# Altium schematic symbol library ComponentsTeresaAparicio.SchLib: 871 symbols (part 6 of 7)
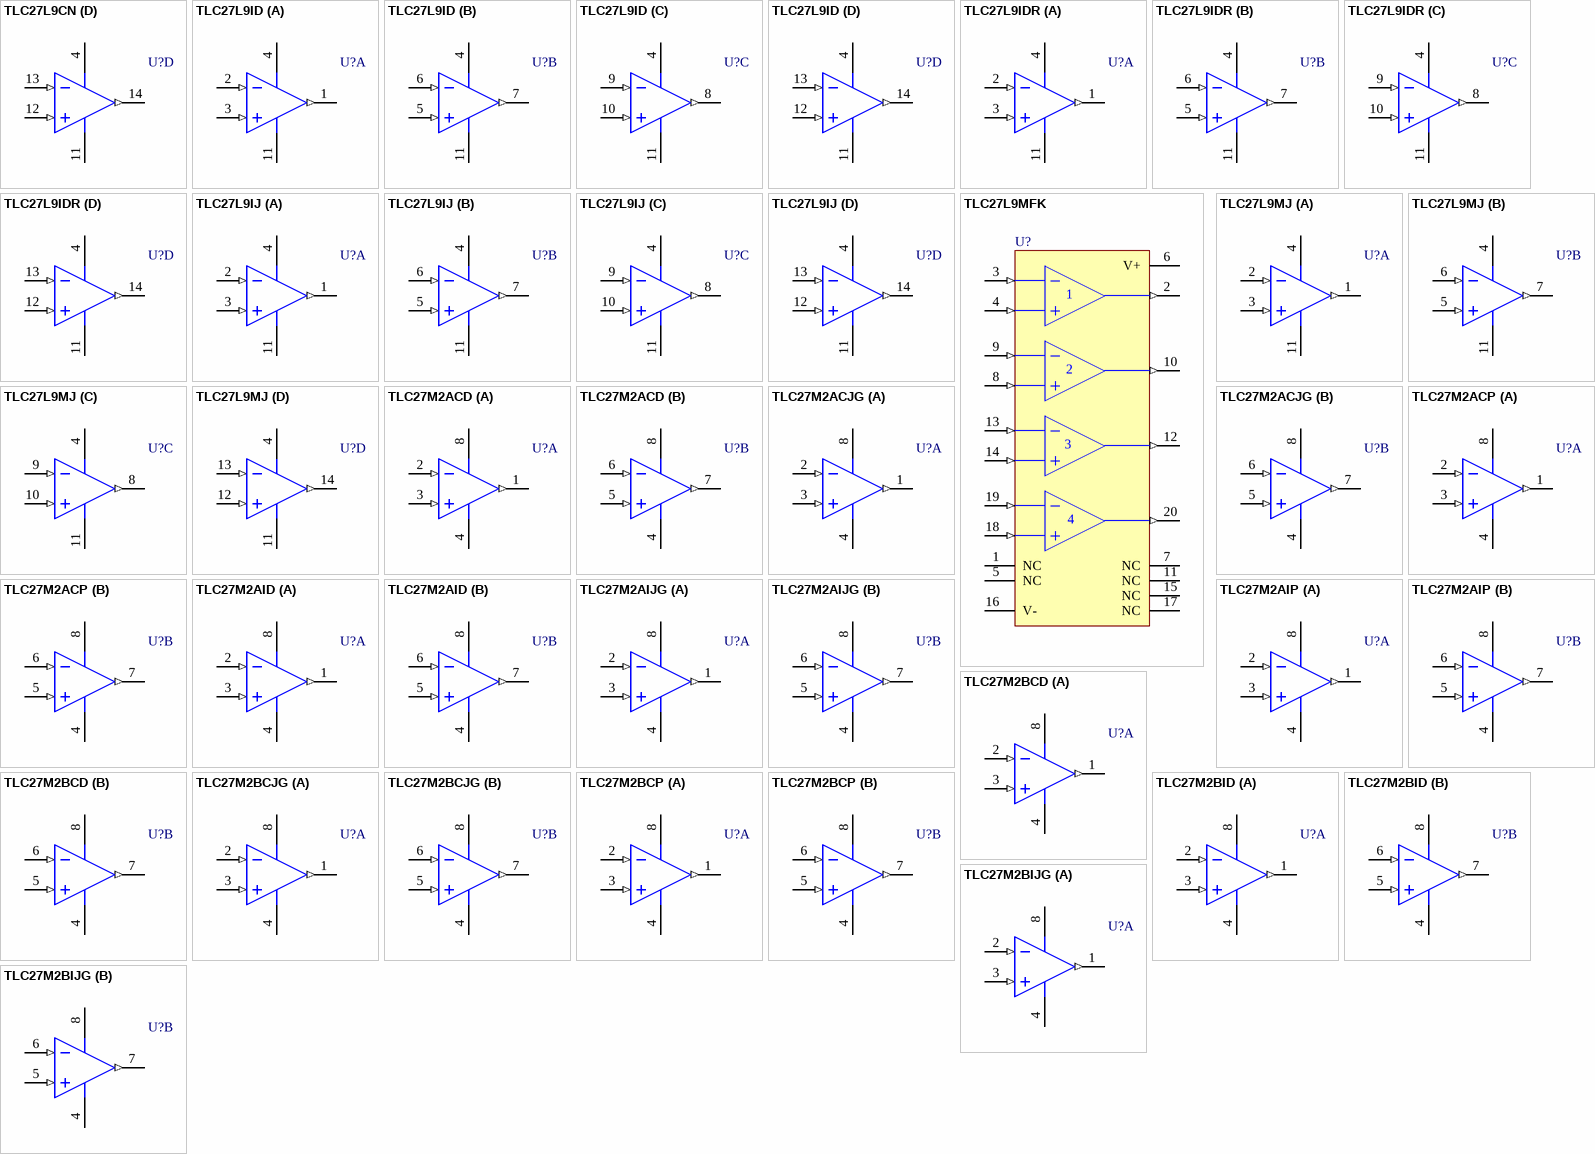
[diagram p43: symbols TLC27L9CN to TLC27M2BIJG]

## TLC27L9MJ
designator U?
LinCMOS Precision Quad Operational Amplifier; ComponentAvailability: Obsolete
footprint J014 (DIP; 14 Leads; Row Spacing 7.62 mm; Pitch 2.54 mm)
3D model J014 (DIP; 14 Leads; Row Spacing 7.62 mm; Pitch 2.54 mm)
pins on every part: 4 V+ (power), 11 V- (power)
part A pins: 1 OUT (out), 2 IN- (in), 3 IN+ (in)
part B pins: 5 IN+ (in), 6 IN- (in), 7 OUT (out)
part C pins: 8 OUT (out), 9 IN- (in), 10 IN+ (in)
part D pins: 12 IN+ (in), 13 IN- (in), 14 OUT (out)

## TLC27M2ACD
designator U?
LinCMOS Precision Dual Operational Amplifier
footprint D008_L (SOIC, 8-Leads, Body 4.9x3.9mm, Pitch 1.27mm, IPC High Density)
footprint D008_M (SOIC, 8-Leads, Body 4.9x3.9mm, Pitch 1.27mm, IPC Low Density)
footprint D008_M (SOIC, 8-Leads, Body 4.9x3.9mm, Pitch 1.27mm, IPC Low Density)
3D model D008 (8-Pin Small Outline Integrated Circuit 1.27 mm Pitch)
pins on every part: 4 GND (power), 8 VDD (power)
part A pins: 1 OUT (out), 2 IN- (in), 3 IN+ (in)
part B pins: 5 IN+ (in), 6 IN- (in), 7 OUT (out)

## TLC27M2ACJG
designator U?
LinCMOS Precision Dual Operational Amplifier
footprint JG008 (DIP; 8 Leads; Row Spacing 7.62 mm; Pitch 2.54 mm)
3D model JG008 (DIP; 8 Leads; Row Spacing 7.62 mm; Pitch 2.54 mm)
pins on every part: 4 GND (power), 8 VDD (power)
part A pins: 1 OUT (out), 2 IN- (in), 3 IN+ (in)
part B pins: 5 IN+ (in), 6 IN- (in), 7 OUT (out)

## TLC27M2ACP
designator U?
LinCMOS Precision Dual Operational Amplifier
footprint P008 (DIP; 8 Leads; Row Spacing 7.62 mm; Pitch 2.54 mm)
3D model P008 (DIP; 8 Leads; Row Spacing 7.62 mm; Pitch 2.54 mm)
pins on every part: 4 GND (power), 8 VDD (power)
part A pins: 1 OUT (out), 2 IN- (in), 3 IN+ (in)
part B pins: 5 IN+ (in), 6 IN- (in), 7 OUT (out)

## TLC27M2AID
designator U?
LinCMOS Precision Dual Operational Amplifier
footprint D008_L (SOIC, 8-Leads, Body 4.9x3.9mm, Pitch 1.27mm, IPC High Density)
footprint D008_M (SOIC, 8-Leads, Body 4.9x3.9mm, Pitch 1.27mm, IPC Low Density)
footprint D008_M (SOIC, 8-Leads, Body 4.9x3.9mm, Pitch 1.27mm, IPC Low Density)
3D model D008 (8-Pin Small Outline Integrated Circuit 1.27 mm Pitch)
pins on every part: 4 GND (power), 8 VDD (power)
part A pins: 1 OUT (out), 2 IN- (in), 3 IN+ (in)
part B pins: 5 IN+ (in), 6 IN- (in), 7 OUT (out)

## TLC27M2AIJG
designator U?
LinCMOS Precision Dual Operational Amplifier
footprint JG008 (DIP; 8 Leads; Row Spacing 7.62 mm; Pitch 2.54 mm)
3D model JG008 (DIP; 8 Leads; Row Spacing 7.62 mm; Pitch 2.54 mm)
pins on every part: 4 GND (power), 8 VDD (power)
part A pins: 1 OUT (out), 2 IN- (in), 3 IN+ (in)
part B pins: 5 IN+ (in), 6 IN- (in), 7 OUT (out)

## TLC27M2AIP
designator U?
LinCMOS Precision Dual Operational Amplifier
footprint P008 (DIP; 8 Leads; Row Spacing 7.62 mm; Pitch 2.54 mm)
3D model P008 (DIP; 8 Leads; Row Spacing 7.62 mm; Pitch 2.54 mm)
pins on every part: 4 GND (power), 8 VDD (power)
part A pins: 1 OUT (out), 2 IN- (in), 3 IN+ (in)
part B pins: 5 IN+ (in), 6 IN- (in), 7 OUT (out)

## TLC27M2BCD
designator U?
LinCMOS Precision Dual Operational Amplifier
footprint D008_L (SOIC, 8-Leads, Body 4.9x3.9mm, Pitch 1.27mm, IPC High Density)
footprint D008_M (SOIC, 8-Leads, Body 4.9x3.9mm, Pitch 1.27mm, IPC Low Density)
footprint D008_M (SOIC, 8-Leads, Body 4.9x3.9mm, Pitch 1.27mm, IPC Low Density)
3D model D008 (8-Pin Small Outline Integrated Circuit 1.27 mm Pitch)
pins on every part: 4 GND (power), 8 VDD (power)
part A pins: 1 OUT (out), 2 IN- (in), 3 IN+ (in)
part B pins: 5 IN+ (in), 6 IN- (in), 7 OUT (out)

## TLC27M2BCJG
designator U?
LinCMOS Precision Dual Operational Amplifier
footprint JG008 (DIP; 8 Leads; Row Spacing 7.62 mm; Pitch 2.54 mm)
3D model JG008 (DIP; 8 Leads; Row Spacing 7.62 mm; Pitch 2.54 mm)
pins on every part: 4 GND (power), 8 VDD (power)
part A pins: 1 OUT (out), 2 IN- (in), 3 IN+ (in)
part B pins: 5 IN+ (in), 6 IN- (in), 7 OUT (out)

## TLC27M2BCP
designator U?
LinCMOS Precision Dual Operational Amplifier
footprint P008 (DIP; 8 Leads; Row Spacing 7.62 mm; Pitch 2.54 mm)
3D model P008 (DIP; 8 Leads; Row Spacing 7.62 mm; Pitch 2.54 mm)
pins on every part: 4 GND (power), 8 VDD (power)
part A pins: 1 OUT (out), 2 IN- (in), 3 IN+ (in)
part B pins: 5 IN+ (in), 6 IN- (in), 7 OUT (out)

## TLC27M2BID
designator U?
LinCMOS Precision Dual Operational Amplifier
footprint D008_L (SOIC, 8-Leads, Body 4.9x3.9mm, Pitch 1.27mm, IPC High Density)
footprint D008_M (SOIC, 8-Leads, Body 4.9x3.9mm, Pitch 1.27mm, IPC Low Density)
footprint D008_M (SOIC, 8-Leads, Body 4.9x3.9mm, Pitch 1.27mm, IPC Low Density)
3D model D008 (8-Pin Small Outline Integrated Circuit 1.27 mm Pitch)
pins on every part: 4 GND (power), 8 VDD (power)
part A pins: 1 OUT (out), 2 IN- (in), 3 IN+ (in)
part B pins: 5 IN+ (in), 6 IN- (in), 7 OUT (out)

## TLC27M2BIJG
designator U?
LinCMOS Precision Dual Operational Amplifier
footprint JG008 (DIP; 8 Leads; Row Spacing 7.62 mm; Pitch 2.54 mm)
3D model JG008 (DIP; 8 Leads; Row Spacing 7.62 mm; Pitch 2.54 mm)
pins on every part: 4 GND (power), 8 VDD (power)
part A pins: 1 OUT (out), 2 IN- (in), 3 IN+ (in)
part B pins: 5 IN+ (in), 6 IN- (in), 7 OUT (out)

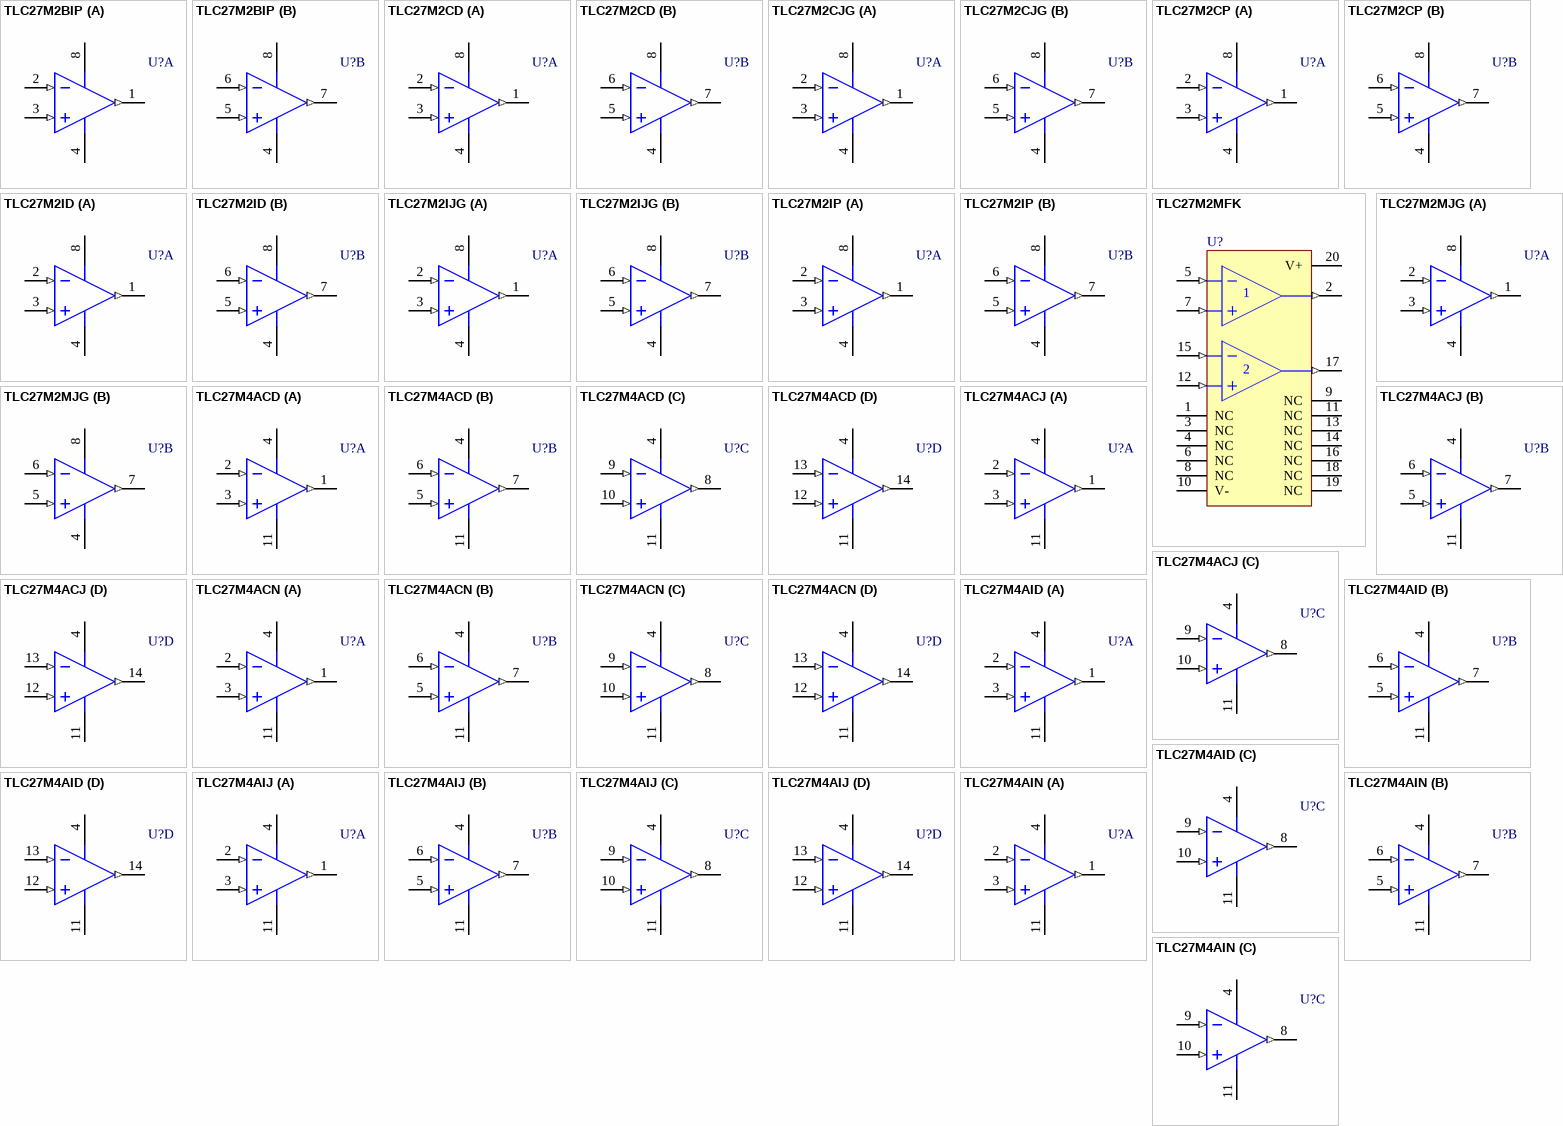
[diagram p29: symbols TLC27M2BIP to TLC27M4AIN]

## TLC27M2BIP
designator U?
LinCMOS Precision Dual Operational Amplifier
footprint P008 (DIP; 8 Leads; Row Spacing 7.62 mm; Pitch 2.54 mm)
3D model P008 (DIP; 8 Leads; Row Spacing 7.62 mm; Pitch 2.54 mm)
pins on every part: 4 GND (power), 8 VDD (power)
part A pins: 1 OUT (out), 2 IN- (in), 3 IN+ (in)
part B pins: 5 IN+ (in), 6 IN- (in), 7 OUT (out)

## TLC27M2CD
designator U?
LinCMOS Precision Dual Operational Amplifier
footprint D008_L (SOIC, 8-Leads, Body 4.9x3.9mm, Pitch 1.27mm, IPC High Density)
footprint D008_M (SOIC, 8-Leads, Body 4.9x3.9mm, Pitch 1.27mm, IPC Low Density)
footprint D008_M (SOIC, 8-Leads, Body 4.9x3.9mm, Pitch 1.27mm, IPC Low Density)
3D model D008 (8-Pin Small Outline Integrated Circuit 1.27 mm Pitch)
pins on every part: 4 GND (power), 8 VDD (power)
part A pins: 1 OUT (out), 2 IN- (in), 3 IN+ (in)
part B pins: 5 IN+ (in), 6 IN- (in), 7 OUT (out)

## TLC27M2CJG
designator U?
LinCMOS Precision Dual Operational Amplifier
footprint JG008 (DIP; 8 Leads; Row Spacing 7.62 mm; Pitch 2.54 mm)
3D model JG008 (DIP; 8 Leads; Row Spacing 7.62 mm; Pitch 2.54 mm)
pins on every part: 4 GND (power), 8 VDD (power)
part A pins: 1 OUT (out), 2 IN- (in), 3 IN+ (in)
part B pins: 5 IN+ (in), 6 IN- (in), 7 OUT (out)

## TLC27M2CP
designator U?
LinCMOS Precision Dual Operational Amplifier
footprint P008 (DIP; 8 Leads; Row Spacing 7.62 mm; Pitch 2.54 mm)
3D model P008 (DIP; 8 Leads; Row Spacing 7.62 mm; Pitch 2.54 mm)
pins on every part: 4 GND (power), 8 VDD (power)
part A pins: 1 OUT (out), 2 IN- (in), 3 IN+ (in)
part B pins: 5 IN+ (in), 6 IN- (in), 7 OUT (out)

## TLC27M2ID
designator U?
LinCMOS Precision Dual Operational Amplifier
footprint D008_L (SOIC, 8-Leads, Body 4.9x3.9mm, Pitch 1.27mm, IPC High Density)
footprint D008_M (SOIC, 8-Leads, Body 4.9x3.9mm, Pitch 1.27mm, IPC Low Density)
footprint D008_M (SOIC, 8-Leads, Body 4.9x3.9mm, Pitch 1.27mm, IPC Low Density)
3D model D008 (8-Pin Small Outline Integrated Circuit 1.27 mm Pitch)
pins on every part: 4 GND (power), 8 VDD (power)
part A pins: 1 OUT (out), 2 IN- (in), 3 IN+ (in)
part B pins: 5 IN+ (in), 6 IN- (in), 7 OUT (out)

## TLC27M2IJG
designator U?
LinCMOS Precision Dual Operational Amplifier
footprint JG008 (DIP; 8 Leads; Row Spacing 7.62 mm; Pitch 2.54 mm)
3D model JG008 (DIP; 8 Leads; Row Spacing 7.62 mm; Pitch 2.54 mm)
pins on every part: 4 GND (power), 8 VDD (power)
part A pins: 1 OUT (out), 2 IN- (in), 3 IN+ (in)
part B pins: 5 IN+ (in), 6 IN- (in), 7 OUT (out)

## TLC27M2IP
designator U?
LinCMOS Precision Dual Operational Amplifier
footprint P008 (DIP; 8 Leads; Row Spacing 7.62 mm; Pitch 2.54 mm)
3D model P008 (DIP; 8 Leads; Row Spacing 7.62 mm; Pitch 2.54 mm)
pins on every part: 4 GND (power), 8 VDD (power)
part A pins: 1 OUT (out), 2 IN- (in), 3 IN+ (in)
part B pins: 5 IN+ (in), 6 IN- (in), 7 OUT (out)

## TLC27M2MFK
designator U?
LinCMOS Precision Dual Operational Amplifier; ComponentAvailability: Obsolete
footprint FK020 (Leadless Chip Carrier; 20 Terminals; Body 8.9 x 8.9 mm)
pins: 1 NC, 2 OUT (out), 3 NC, 4 NC, 5 IN- (in), 6 NC, 7 IN+ (in), 8 NC, 9 NC, 10 V- (power), 11 NC, 12 IN+ (in), 13 NC, 14 NC, 15 IN- (in), 16 NC, 17 OUT (out), 18 NC, 19 NC, 20 V+ (power)

## TLC27M2MJG
designator U?
LinCMOS Precision Dual Operational Amplifier; ComponentAvailability: Obsolete
footprint JG008 (DIP; 8 Leads; Row Spacing 7.62 mm; Pitch 2.54 mm)
3D model JG008 (DIP; 8 Leads; Row Spacing 7.62 mm; Pitch 2.54 mm)
pins on every part: 4 GND (power), 8 VDD (power)
part A pins: 1 OUT (out), 2 IN- (in), 3 IN+ (in)
part B pins: 5 IN+ (in), 6 IN- (in), 7 OUT (out)

## TLC27M4ACD
designator U?
LinCMOS Precision Quad Operational Amplifier
footprint D014_N (SOIC, 14-Leads, Body 8.7x3.9mm, Pitch 1.27mm, IPC Medium Density)
footprint D014_L (SOIC, 14-Leads, Body 8.7x3.9mm, Pitch 1.27mm, IPC High Density)
footprint D014_M (SOIC, 14-Leads, Body 8.7x3.9mm, Pitch 1.27mm, IPC Low Density)
3D model D014 (14-Pin Small Outline Integrated Circuit 1.27 mm Pitch)
pins on every part: 4 V+ (power), 11 V- (power)
part A pins: 1 OUT (out), 2 IN- (in), 3 IN+ (in)
part B pins: 5 IN+ (in), 6 IN- (in), 7 OUT (out)
part C pins: 8 OUT (out), 9 IN- (in), 10 IN+ (in)
part D pins: 12 IN+ (in), 13 IN- (in), 14 OUT (out)

## TLC27M4ACJ
designator U?
LinCMOS Precision Quad Operational Amplifier
footprint J014 (DIP; 14 Leads; Row Spacing 7.62 mm; Pitch 2.54 mm)
3D model J014 (DIP; 14 Leads; Row Spacing 7.62 mm; Pitch 2.54 mm)
pins on every part: 4 V+ (power), 11 V- (power)
part A pins: 1 OUT (out), 2 IN- (in), 3 IN+ (in)
part B pins: 5 IN+ (in), 6 IN- (in), 7 OUT (out)
part C pins: 8 OUT (out), 9 IN- (in), 10 IN+ (in)
part D pins: 12 IN+ (in), 13 IN- (in), 14 OUT (out)

## TLC27M4ACN
designator U?
LinCMOS Precision Quad Operational Amplifier
footprint N014 (DIP; 14 Leads; Row Spacing 7.62 mm; Pitch 2.54 mm)
3D model N014 (DIP; 14 Leads; Row Spacing 7.62 mm; Pitch 2.54 mm)
pins on every part: 4 V+ (power), 11 V- (power)
part A pins: 1 OUT (out), 2 IN- (in), 3 IN+ (in)
part B pins: 5 IN+ (in), 6 IN- (in), 7 OUT (out)
part C pins: 8 OUT (out), 9 IN- (in), 10 IN+ (in)
part D pins: 12 IN+ (in), 13 IN- (in), 14 OUT (out)

## TLC27M4AID
designator U?
LinCMOS Precision Quad Operational Amplifier
footprint D014_N (SOIC, 14-Leads, Body 8.7x3.9mm, Pitch 1.27mm, IPC Medium Density)
footprint D014_L (SOIC, 14-Leads, Body 8.7x3.9mm, Pitch 1.27mm, IPC High Density)
footprint D014_M (SOIC, 14-Leads, Body 8.7x3.9mm, Pitch 1.27mm, IPC Low Density)
3D model D014 (14-Pin Small Outline Integrated Circuit 1.27 mm Pitch)
pins on every part: 4 V+ (power), 11 V- (power)
part A pins: 1 OUT (out), 2 IN- (in), 3 IN+ (in)
part B pins: 5 IN+ (in), 6 IN- (in), 7 OUT (out)
part C pins: 8 OUT (out), 9 IN- (in), 10 IN+ (in)
part D pins: 12 IN+ (in), 13 IN- (in), 14 OUT (out)

## TLC27M4AIJ
designator U?
LinCMOS Precision Quad Operational Amplifier
footprint J014 (DIP; 14 Leads; Row Spacing 7.62 mm; Pitch 2.54 mm)
3D model J014 (DIP; 14 Leads; Row Spacing 7.62 mm; Pitch 2.54 mm)
pins on every part: 4 V+ (power), 11 V- (power)
part A pins: 1 OUT (out), 2 IN- (in), 3 IN+ (in)
part B pins: 5 IN+ (in), 6 IN- (in), 7 OUT (out)
part C pins: 8 OUT (out), 9 IN- (in), 10 IN+ (in)
part D pins: 12 IN+ (in), 13 IN- (in), 14 OUT (out)

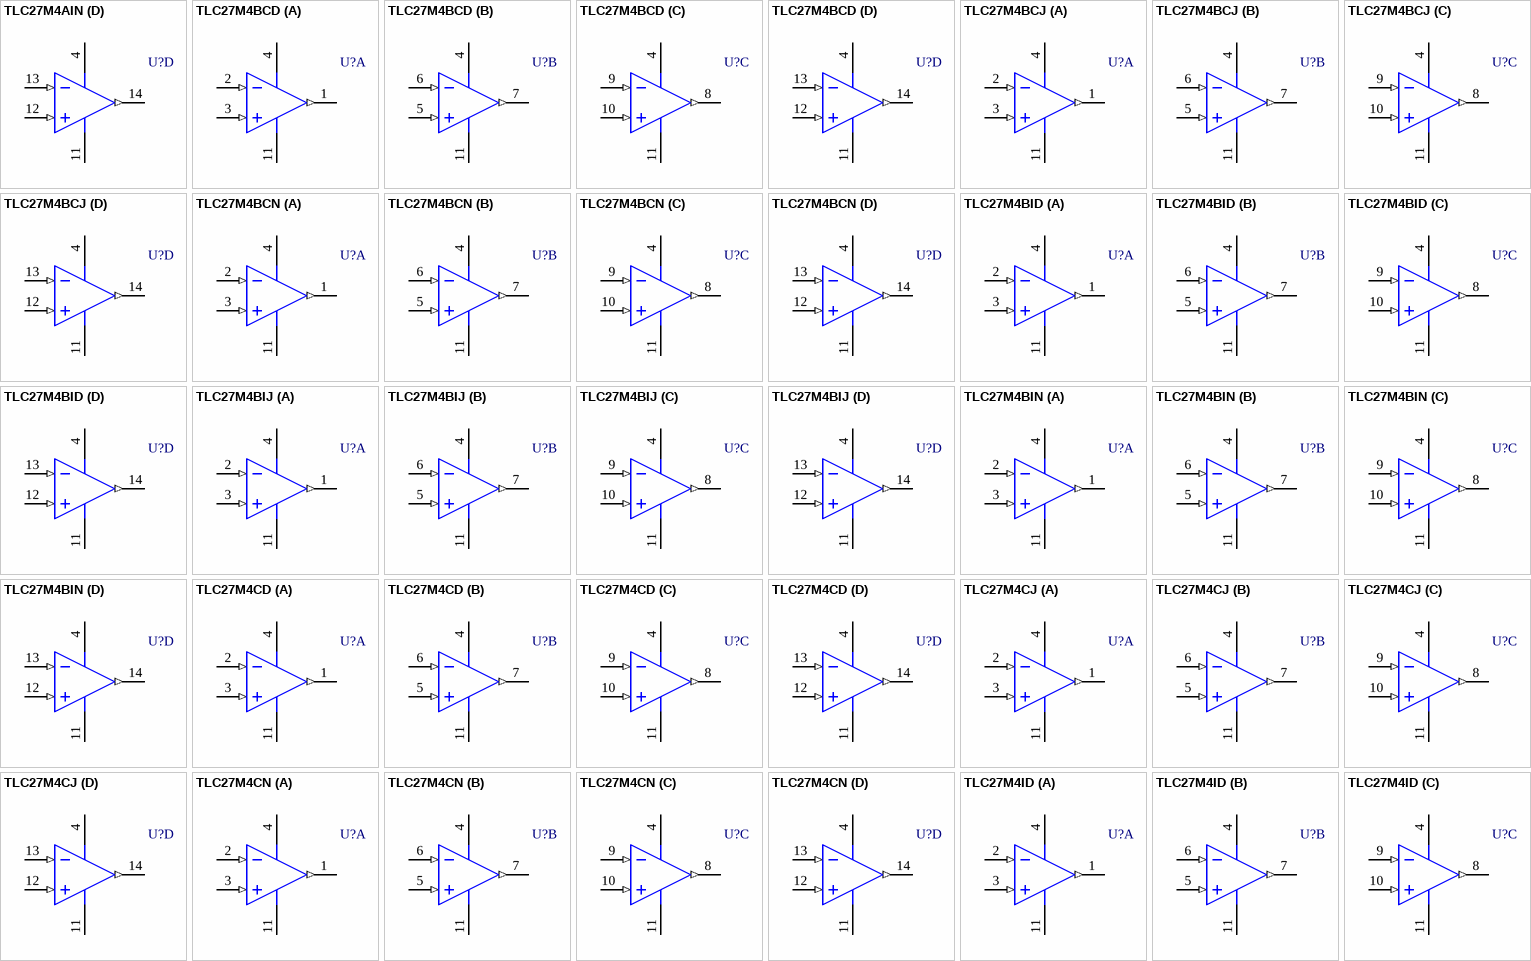
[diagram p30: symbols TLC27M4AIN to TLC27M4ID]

## TLC27M4AIN
designator U?
LinCMOS Precision Quad Operational Amplifier
footprint N014 (DIP; 14 Leads; Row Spacing 7.62 mm; Pitch 2.54 mm)
3D model N014 (DIP; 14 Leads; Row Spacing 7.62 mm; Pitch 2.54 mm)
pins on every part: 4 V+ (power), 11 V- (power)
part A pins: 1 OUT (out), 2 IN- (in), 3 IN+ (in)
part B pins: 5 IN+ (in), 6 IN- (in), 7 OUT (out)
part C pins: 8 OUT (out), 9 IN- (in), 10 IN+ (in)
part D pins: 12 IN+ (in), 13 IN- (in), 14 OUT (out)

## TLC27M4BCD
designator U?
LinCMOS Precision Quad Operational Amplifier
footprint D014_N (SOIC, 14-Leads, Body 8.7x3.9mm, Pitch 1.27mm, IPC Medium Density)
footprint D014_L (SOIC, 14-Leads, Body 8.7x3.9mm, Pitch 1.27mm, IPC High Density)
footprint D014_M (SOIC, 14-Leads, Body 8.7x3.9mm, Pitch 1.27mm, IPC Low Density)
3D model D014 (14-Pin Small Outline Integrated Circuit 1.27 mm Pitch)
pins on every part: 4 V+ (power), 11 V- (power)
part A pins: 1 OUT (out), 2 IN- (in), 3 IN+ (in)
part B pins: 5 IN+ (in), 6 IN- (in), 7 OUT (out)
part C pins: 8 OUT (out), 9 IN- (in), 10 IN+ (in)
part D pins: 12 IN+ (in), 13 IN- (in), 14 OUT (out)

## TLC27M4BCJ
designator U?
LinCMOS Precision Quad Operational Amplifier
footprint J014 (DIP; 14 Leads; Row Spacing 7.62 mm; Pitch 2.54 mm)
3D model J014 (DIP; 14 Leads; Row Spacing 7.62 mm; Pitch 2.54 mm)
pins on every part: 4 V+ (power), 11 V- (power)
part A pins: 1 OUT (out), 2 IN- (in), 3 IN+ (in)
part B pins: 5 IN+ (in), 6 IN- (in), 7 OUT (out)
part C pins: 8 OUT (out), 9 IN- (in), 10 IN+ (in)
part D pins: 12 IN+ (in), 13 IN- (in), 14 OUT (out)

## TLC27M4BCN
designator U?
LinCMOS Precision Quad Operational Amplifier
footprint N014 (DIP; 14 Leads; Row Spacing 7.62 mm; Pitch 2.54 mm)
3D model N014 (DIP; 14 Leads; Row Spacing 7.62 mm; Pitch 2.54 mm)
pins on every part: 4 V+ (power), 11 V- (power)
part A pins: 1 OUT (out), 2 IN- (in), 3 IN+ (in)
part B pins: 5 IN+ (in), 6 IN- (in), 7 OUT (out)
part C pins: 8 OUT (out), 9 IN- (in), 10 IN+ (in)
part D pins: 12 IN+ (in), 13 IN- (in), 14 OUT (out)

## TLC27M4BID
designator U?
LinCMOS Precision Quad Operational Amplifier
footprint D014_N (SOIC, 14-Leads, Body 8.7x3.9mm, Pitch 1.27mm, IPC Medium Density)
footprint D014_L (SOIC, 14-Leads, Body 8.7x3.9mm, Pitch 1.27mm, IPC High Density)
footprint D014_M (SOIC, 14-Leads, Body 8.7x3.9mm, Pitch 1.27mm, IPC Low Density)
3D model D014 (14-Pin Small Outline Integrated Circuit 1.27 mm Pitch)
pins on every part: 4 V+ (power), 11 V- (power)
part A pins: 1 OUT (out), 2 IN- (in), 3 IN+ (in)
part B pins: 5 IN+ (in), 6 IN- (in), 7 OUT (out)
part C pins: 8 OUT (out), 9 IN- (in), 10 IN+ (in)
part D pins: 12 IN+ (in), 13 IN- (in), 14 OUT (out)

## TLC27M4BIJ
designator U?
LinCMOS Precision Quad Operational Amplifier
footprint J014 (DIP; 14 Leads; Row Spacing 7.62 mm; Pitch 2.54 mm)
3D model J014 (DIP; 14 Leads; Row Spacing 7.62 mm; Pitch 2.54 mm)
pins on every part: 4 V+ (power), 11 V- (power)
part A pins: 1 OUT (out), 2 IN- (in), 3 IN+ (in)
part B pins: 5 IN+ (in), 6 IN- (in), 7 OUT (out)
part C pins: 8 OUT (out), 9 IN- (in), 10 IN+ (in)
part D pins: 12 IN+ (in), 13 IN- (in), 14 OUT (out)

## TLC27M4BIN
designator U?
LinCMOS Precision Quad Operational Amplifier
footprint N014 (DIP; 14 Leads; Row Spacing 7.62 mm; Pitch 2.54 mm)
3D model N014 (DIP; 14 Leads; Row Spacing 7.62 mm; Pitch 2.54 mm)
pins on every part: 4 V+ (power), 11 V- (power)
part A pins: 1 OUT (out), 2 IN- (in), 3 IN+ (in)
part B pins: 5 IN+ (in), 6 IN- (in), 7 OUT (out)
part C pins: 8 OUT (out), 9 IN- (in), 10 IN+ (in)
part D pins: 12 IN+ (in), 13 IN- (in), 14 OUT (out)

## TLC27M4CD
designator U?
LinCMOS Precision Quad Operational Amplifier
footprint D014_N (SOIC, 14-Leads, Body 8.7x3.9mm, Pitch 1.27mm, IPC Medium Density)
footprint D014_L (SOIC, 14-Leads, Body 8.7x3.9mm, Pitch 1.27mm, IPC High Density)
footprint D014_M (SOIC, 14-Leads, Body 8.7x3.9mm, Pitch 1.27mm, IPC Low Density)
3D model D014 (14-Pin Small Outline Integrated Circuit 1.27 mm Pitch)
pins on every part: 4 V+ (power), 11 V- (power)
part A pins: 1 OUT (out), 2 IN- (in), 3 IN+ (in)
part B pins: 5 IN+ (in), 6 IN- (in), 7 OUT (out)
part C pins: 8 OUT (out), 9 IN- (in), 10 IN+ (in)
part D pins: 12 IN+ (in), 13 IN- (in), 14 OUT (out)

## TLC27M4CJ
designator U?
LinCMOS Precision Quad Operational Amplifier
footprint J014 (DIP; 14 Leads; Row Spacing 7.62 mm; Pitch 2.54 mm)
3D model J014 (DIP; 14 Leads; Row Spacing 7.62 mm; Pitch 2.54 mm)
pins on every part: 4 V+ (power), 11 V- (power)
part A pins: 1 OUT (out), 2 IN- (in), 3 IN+ (in)
part B pins: 5 IN+ (in), 6 IN- (in), 7 OUT (out)
part C pins: 8 OUT (out), 9 IN- (in), 10 IN+ (in)
part D pins: 12 IN+ (in), 13 IN- (in), 14 OUT (out)

## TLC27M4CN
designator U?
LinCMOS Precision Quad Operational Amplifier
footprint N014 (DIP; 14 Leads; Row Spacing 7.62 mm; Pitch 2.54 mm)
3D model N014 (DIP; 14 Leads; Row Spacing 7.62 mm; Pitch 2.54 mm)
pins on every part: 4 V+ (power), 11 V- (power)
part A pins: 1 OUT (out), 2 IN- (in), 3 IN+ (in)
part B pins: 5 IN+ (in), 6 IN- (in), 7 OUT (out)
part C pins: 8 OUT (out), 9 IN- (in), 10 IN+ (in)
part D pins: 12 IN+ (in), 13 IN- (in), 14 OUT (out)

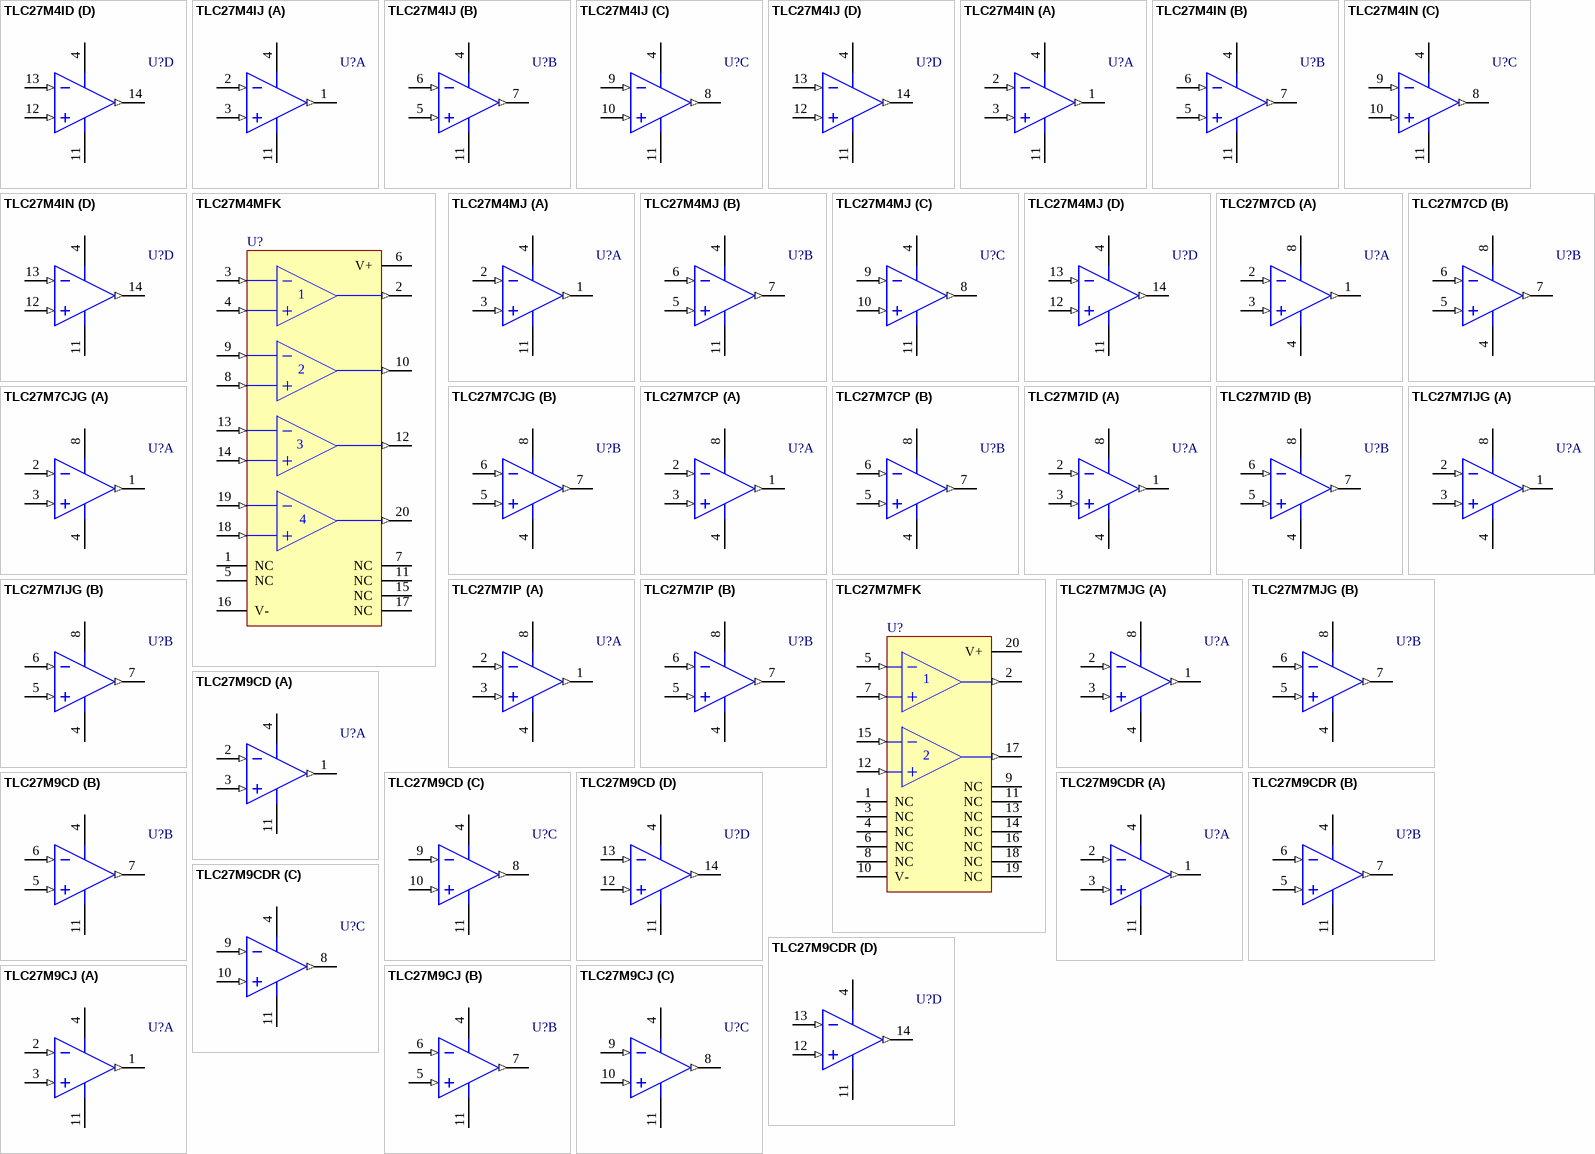
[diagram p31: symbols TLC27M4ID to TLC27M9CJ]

## TLC27M4ID
designator U?
LinCMOS Precision Quad Operational Amplifier
footprint D014_N (SOIC, 14-Leads, Body 8.7x3.9mm, Pitch 1.27mm, IPC Medium Density)
footprint D014_L (SOIC, 14-Leads, Body 8.7x3.9mm, Pitch 1.27mm, IPC High Density)
footprint D014_M (SOIC, 14-Leads, Body 8.7x3.9mm, Pitch 1.27mm, IPC Low Density)
3D model D014 (14-Pin Small Outline Integrated Circuit 1.27 mm Pitch)
pins on every part: 4 V+ (power), 11 V- (power)
part A pins: 1 OUT (out), 2 IN- (in), 3 IN+ (in)
part B pins: 5 IN+ (in), 6 IN- (in), 7 OUT (out)
part C pins: 8 OUT (out), 9 IN- (in), 10 IN+ (in)
part D pins: 12 IN+ (in), 13 IN- (in), 14 OUT (out)

## TLC27M4IJ
designator U?
LinCMOS Precision Quad Operational Amplifier
footprint J014 (DIP; 14 Leads; Row Spacing 7.62 mm; Pitch 2.54 mm)
3D model J014 (DIP; 14 Leads; Row Spacing 7.62 mm; Pitch 2.54 mm)
pins on every part: 4 V+ (power), 11 V- (power)
part A pins: 1 OUT (out), 2 IN- (in), 3 IN+ (in)
part B pins: 5 IN+ (in), 6 IN- (in), 7 OUT (out)
part C pins: 8 OUT (out), 9 IN- (in), 10 IN+ (in)
part D pins: 12 IN+ (in), 13 IN- (in), 14 OUT (out)

## TLC27M4IN
designator U?
LinCMOS Precision Quad Operational Amplifier
footprint N014 (DIP; 14 Leads; Row Spacing 7.62 mm; Pitch 2.54 mm)
3D model N014 (DIP; 14 Leads; Row Spacing 7.62 mm; Pitch 2.54 mm)
pins on every part: 4 V+ (power), 11 V- (power)
part A pins: 1 OUT (out), 2 IN- (in), 3 IN+ (in)
part B pins: 5 IN+ (in), 6 IN- (in), 7 OUT (out)
part C pins: 8 OUT (out), 9 IN- (in), 10 IN+ (in)
part D pins: 12 IN+ (in), 13 IN- (in), 14 OUT (out)

## TLC27M4MFK
designator U?
LinCMOS Precision Quad Operational Amplifier; ComponentAvailability: Obsolete
footprint FK020 (Leadless Chip Carrier; 20 Terminals; Body 8.9 x 8.9 mm)
pins: 1 NC, 2 OUT (out), 3 IN- (in), 4 IN+ (in), 5 NC, 6 V+ (power), 7 NC, 8 IN+ (in), 9 IN- (in), 10 OUT (out), 11 NC, 12 OUT (out), 13 IN- (in), 14 IN+ (in), 15 NC, 16 V- (power), 17 NC, 18 IN+ (in), 19 IN- (in), 20 OUT (out)

## TLC27M4MJ
designator U?
LinCMOS Precision Quad Operational Amplifier; ComponentAvailability: Obsolete
footprint J014 (DIP; 14 Leads; Row Spacing 7.62 mm; Pitch 2.54 mm)
3D model J014 (DIP; 14 Leads; Row Spacing 7.62 mm; Pitch 2.54 mm)
pins on every part: 4 V+ (power), 11 V- (power)
part A pins: 1 OUT (out), 2 IN- (in), 3 IN+ (in)
part B pins: 5 IN+ (in), 6 IN- (in), 7 OUT (out)
part C pins: 8 OUT (out), 9 IN- (in), 10 IN+ (in)
part D pins: 12 IN+ (in), 13 IN- (in), 14 OUT (out)

## TLC27M7CD
designator U?
LinCMOS Precision Dual Operational Amplifier
footprint D008_L (SOIC, 8-Leads, Body 4.9x3.9mm, Pitch 1.27mm, IPC High Density)
footprint D008_M (SOIC, 8-Leads, Body 4.9x3.9mm, Pitch 1.27mm, IPC Low Density)
footprint D008_M (SOIC, 8-Leads, Body 4.9x3.9mm, Pitch 1.27mm, IPC Low Density)
3D model D008 (8-Pin Small Outline Integrated Circuit 1.27 mm Pitch)
pins on every part: 4 GND (power), 8 VDD (power)
part A pins: 1 OUT (out), 2 IN- (in), 3 IN+ (in)
part B pins: 5 IN+ (in), 6 IN- (in), 7 OUT (out)

## TLC27M7CJG
designator U?
LinCMOS Precision Dual Operational Amplifier
footprint JG008 (DIP; 8 Leads; Row Spacing 7.62 mm; Pitch 2.54 mm)
3D model JG008 (DIP; 8 Leads; Row Spacing 7.62 mm; Pitch 2.54 mm)
pins on every part: 4 GND (power), 8 VDD (power)
part A pins: 1 OUT (out), 2 IN- (in), 3 IN+ (in)
part B pins: 5 IN+ (in), 6 IN- (in), 7 OUT (out)

## TLC27M7CP
designator U?
LinCMOS Precision Dual Operational Amplifier
footprint P008 (DIP; 8 Leads; Row Spacing 7.62 mm; Pitch 2.54 mm)
3D model P008 (DIP; 8 Leads; Row Spacing 7.62 mm; Pitch 2.54 mm)
pins on every part: 4 GND (power), 8 VDD (power)
part A pins: 1 OUT (out), 2 IN- (in), 3 IN+ (in)
part B pins: 5 IN+ (in), 6 IN- (in), 7 OUT (out)

## TLC27M7ID
designator U?
LinCMOS Precision Dual Operational Amplifier
footprint D008_L (SOIC, 8-Leads, Body 4.9x3.9mm, Pitch 1.27mm, IPC High Density)
footprint D008_M (SOIC, 8-Leads, Body 4.9x3.9mm, Pitch 1.27mm, IPC Low Density)
footprint D008_M (SOIC, 8-Leads, Body 4.9x3.9mm, Pitch 1.27mm, IPC Low Density)
3D model D008 (8-Pin Small Outline Integrated Circuit 1.27 mm Pitch)
pins on every part: 4 GND (power), 8 VDD (power)
part A pins: 1 OUT (out), 2 IN- (in), 3 IN+ (in)
part B pins: 5 IN+ (in), 6 IN- (in), 7 OUT (out)

## TLC27M7IJG
designator U?
LinCMOS Precision Dual Operational Amplifier
footprint JG008 (DIP; 8 Leads; Row Spacing 7.62 mm; Pitch 2.54 mm)
3D model JG008 (DIP; 8 Leads; Row Spacing 7.62 mm; Pitch 2.54 mm)
pins on every part: 4 GND (power), 8 VDD (power)
part A pins: 1 OUT (out), 2 IN- (in), 3 IN+ (in)
part B pins: 5 IN+ (in), 6 IN- (in), 7 OUT (out)

## TLC27M7IP
designator U?
LinCMOS Precision Dual Operational Amplifier
footprint P008 (DIP; 8 Leads; Row Spacing 7.62 mm; Pitch 2.54 mm)
3D model P008 (DIP; 8 Leads; Row Spacing 7.62 mm; Pitch 2.54 mm)
pins on every part: 4 GND (power), 8 VDD (power)
part A pins: 1 OUT (out), 2 IN- (in), 3 IN+ (in)
part B pins: 5 IN+ (in), 6 IN- (in), 7 OUT (out)

## TLC27M7MFK
designator U?
LinCMOS Precision Quad Operational Amplifier; ComponentAvailability: Obsolete
footprint FK020 (Leadless Chip Carrier; 20 Terminals; Body 8.9 x 8.9 mm)
pins: 1 NC, 2 OUT (out), 3 NC, 4 NC, 5 IN- (in), 6 NC, 7 IN+ (in), 8 NC, 9 NC, 10 V- (power), 11 NC, 12 IN+ (in), 13 NC, 14 NC, 15 IN- (in), 16 NC, 17 OUT (out), 18 NC, 19 NC, 20 V+ (power)

## TLC27M7MJG
designator U?
LinCMOS Precision Dual Operational Amplifier; ComponentAvailability: Obsolete
footprint JG008 (DIP; 8 Leads; Row Spacing 7.62 mm; Pitch 2.54 mm)
3D model JG008 (DIP; 8 Leads; Row Spacing 7.62 mm; Pitch 2.54 mm)
pins on every part: 4 GND (power), 8 VDD (power)
part A pins: 1 OUT (out), 2 IN- (in), 3 IN+ (in)
part B pins: 5 IN+ (in), 6 IN- (in), 7 OUT (out)

## TLC27M9CD
designator U?
LinCMOS Precision Quad Operational Amplifier
footprint D014_N (SOIC, 14-Leads, Body 8.7x3.9mm, Pitch 1.27mm, IPC Medium Density)
footprint D014_L (SOIC, 14-Leads, Body 8.7x3.9mm, Pitch 1.27mm, IPC High Density)
footprint D014_M (SOIC, 14-Leads, Body 8.7x3.9mm, Pitch 1.27mm, IPC Low Density)
3D model D014 (14-Pin Small Outline Integrated Circuit 1.27 mm Pitch)
pins on every part: 4 V+ (power), 11 V- (power)
part A pins: 1 OUT (out), 2 IN- (in), 3 IN+ (in)
part B pins: 5 IN+ (in), 6 IN- (in), 7 OUT (out)
part C pins: 8 OUT (out), 9 IN- (in), 10 IN+ (in)
part D pins: 12 IN+ (in), 13 IN- (in), 14 OUT (out)

## TLC27M9CDR
designator U?
LinCMOS Precision Quad Operational Amplifier
footprint D014_N (SOIC, 14-Leads, Body 8.7x3.9mm, Pitch 1.27mm, IPC Medium Density)
footprint D014_L (SOIC, 14-Leads, Body 8.7x3.9mm, Pitch 1.27mm, IPC High Density)
footprint D014_M (SOIC, 14-Leads, Body 8.7x3.9mm, Pitch 1.27mm, IPC Low Density)
3D model D014 (14-Pin Small Outline Integrated Circuit 1.27 mm Pitch)
pins on every part: 4 V+ (power), 11 V- (power)
part A pins: 1 OUT (out), 2 IN- (in), 3 IN+ (in)
part B pins: 5 IN+ (in), 6 IN- (in), 7 OUT (out)
part C pins: 8 OUT (out), 9 IN- (in), 10 IN+ (in)
part D pins: 12 IN+ (in), 13 IN- (in), 14 OUT (out)

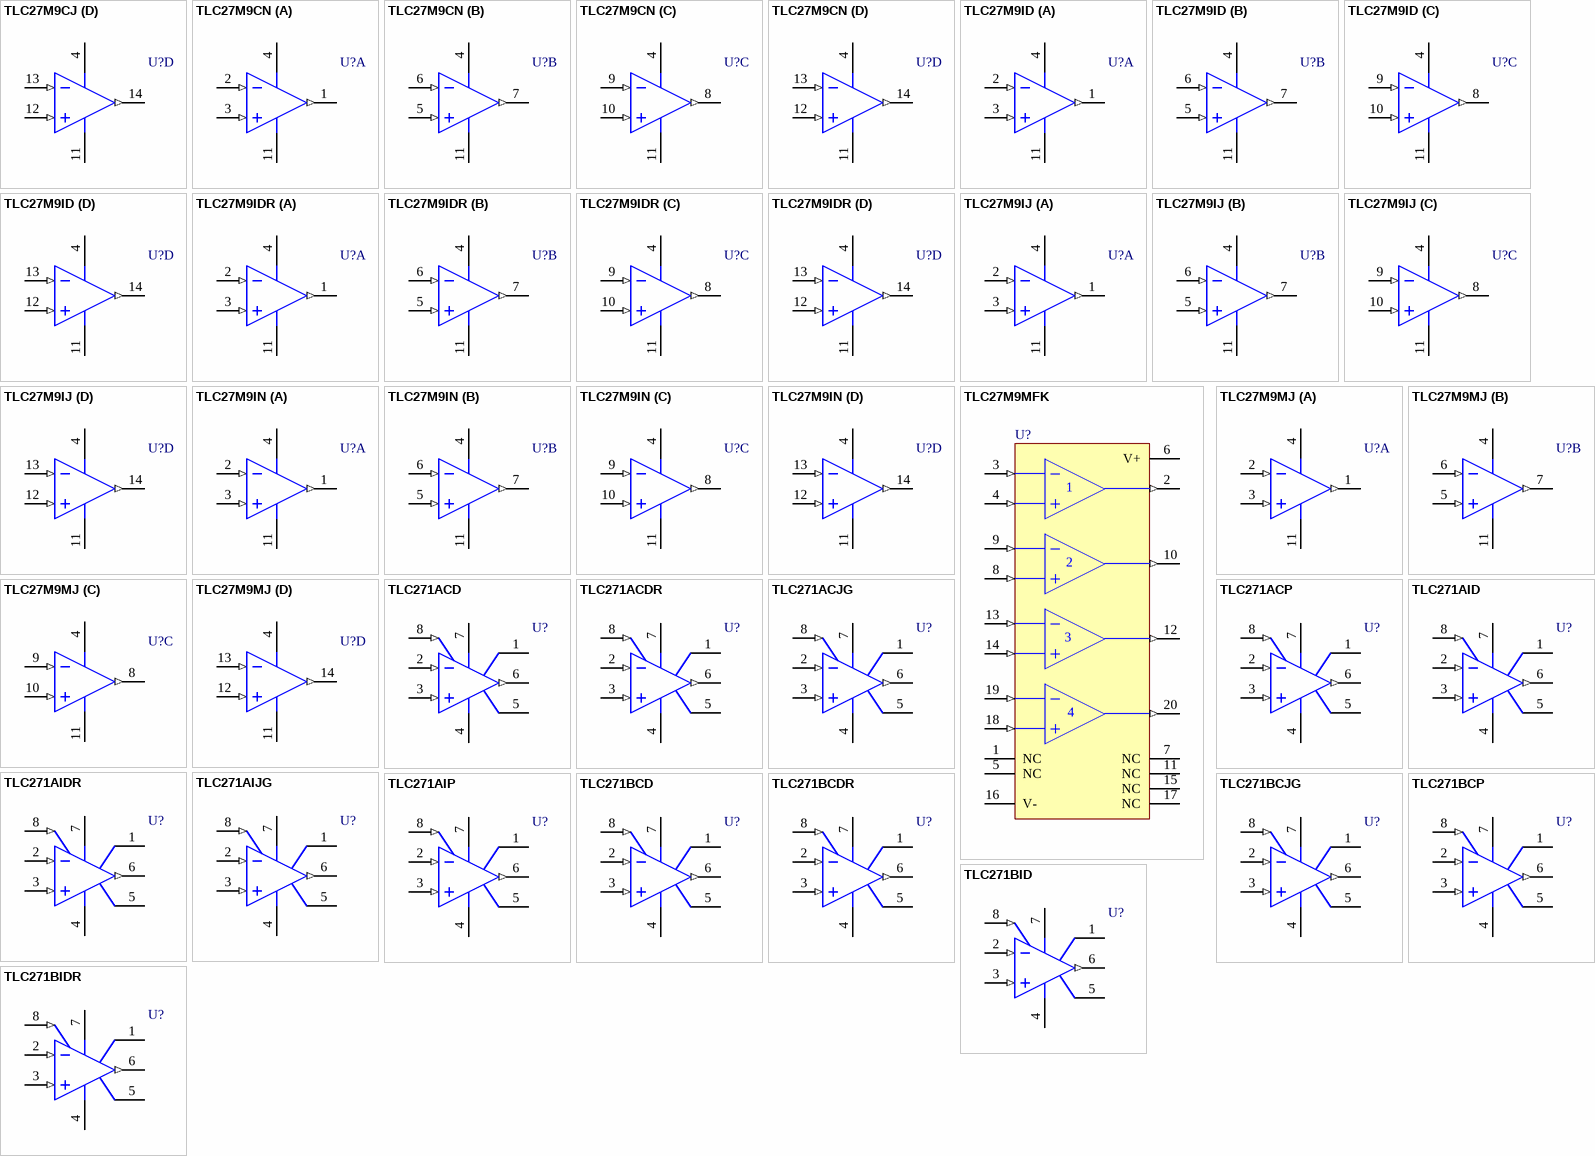
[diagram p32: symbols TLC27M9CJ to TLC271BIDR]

## TLC27M9CJ
designator U?
LinCMOS Precision Quad Operational Amplifier
footprint J014 (DIP; 14 Leads; Row Spacing 7.62 mm; Pitch 2.54 mm)
3D model J014 (DIP; 14 Leads; Row Spacing 7.62 mm; Pitch 2.54 mm)
pins on every part: 4 V+ (power), 11 V- (power)
part A pins: 1 OUT (out), 2 IN- (in), 3 IN+ (in)
part B pins: 5 IN+ (in), 6 IN- (in), 7 OUT (out)
part C pins: 8 OUT (out), 9 IN- (in), 10 IN+ (in)
part D pins: 12 IN+ (in), 13 IN- (in), 14 OUT (out)

## TLC27M9CN
designator U?
LinCMOS Precision Quad Operational Amplifier
footprint N014 (DIP; 14 Leads; Row Spacing 7.62 mm; Pitch 2.54 mm)
3D model N014 (DIP; 14 Leads; Row Spacing 7.62 mm; Pitch 2.54 mm)
pins on every part: 4 V+ (power), 11 V- (power)
part A pins: 1 OUT (out), 2 IN- (in), 3 IN+ (in)
part B pins: 5 IN+ (in), 6 IN- (in), 7 OUT (out)
part C pins: 8 OUT (out), 9 IN- (in), 10 IN+ (in)
part D pins: 12 IN+ (in), 13 IN- (in), 14 OUT (out)

## TLC27M9ID
designator U?
LinCMOS Precision Quad Operational Amplifier
footprint D014_N (SOIC, 14-Leads, Body 8.7x3.9mm, Pitch 1.27mm, IPC Medium Density)
footprint D014_L (SOIC, 14-Leads, Body 8.7x3.9mm, Pitch 1.27mm, IPC High Density)
footprint D014_M (SOIC, 14-Leads, Body 8.7x3.9mm, Pitch 1.27mm, IPC Low Density)
3D model D014 (14-Pin Small Outline Integrated Circuit 1.27 mm Pitch)
pins on every part: 4 V+ (power), 11 V- (power)
part A pins: 1 OUT (out), 2 IN- (in), 3 IN+ (in)
part B pins: 5 IN+ (in), 6 IN- (in), 7 OUT (out)
part C pins: 8 OUT (out), 9 IN- (in), 10 IN+ (in)
part D pins: 12 IN+ (in), 13 IN- (in), 14 OUT (out)

## TLC27M9IDR
designator U?
LinCMOS Precision Quad Operational Amplifier
footprint D014_N (SOIC, 14-Leads, Body 8.7x3.9mm, Pitch 1.27mm, IPC Medium Density)
footprint D014_L (SOIC, 14-Leads, Body 8.7x3.9mm, Pitch 1.27mm, IPC High Density)
footprint D014_M (SOIC, 14-Leads, Body 8.7x3.9mm, Pitch 1.27mm, IPC Low Density)
3D model D014 (14-Pin Small Outline Integrated Circuit 1.27 mm Pitch)
pins on every part: 4 V+ (power), 11 V- (power)
part A pins: 1 OUT (out), 2 IN- (in), 3 IN+ (in)
part B pins: 5 IN+ (in), 6 IN- (in), 7 OUT (out)
part C pins: 8 OUT (out), 9 IN- (in), 10 IN+ (in)
part D pins: 12 IN+ (in), 13 IN- (in), 14 OUT (out)

## TLC27M9IJ
designator U?
LinCMOS Precision Quad Operational Amplifier
footprint J014 (DIP; 14 Leads; Row Spacing 7.62 mm; Pitch 2.54 mm)
3D model J014 (DIP; 14 Leads; Row Spacing 7.62 mm; Pitch 2.54 mm)
pins on every part: 4 V+ (power), 11 V- (power)
part A pins: 1 OUT (out), 2 IN- (in), 3 IN+ (in)
part B pins: 5 IN+ (in), 6 IN- (in), 7 OUT (out)
part C pins: 8 OUT (out), 9 IN- (in), 10 IN+ (in)
part D pins: 12 IN+ (in), 13 IN- (in), 14 OUT (out)

## TLC27M9IN
designator U?
LinCMOS Precision Quad Operational Amplifier
footprint N014 (DIP; 14 Leads; Row Spacing 7.62 mm; Pitch 2.54 mm)
3D model N014 (DIP; 14 Leads; Row Spacing 7.62 mm; Pitch 2.54 mm)
pins on every part: 4 V+ (power), 11 V- (power)
part A pins: 1 OUT (out), 2 IN- (in), 3 IN+ (in)
part B pins: 5 IN+ (in), 6 IN- (in), 7 OUT (out)
part C pins: 8 OUT (out), 9 IN- (in), 10 IN+ (in)
part D pins: 12 IN+ (in), 13 IN- (in), 14 OUT (out)

## TLC27M9MFK
designator U?
LinCMOS Precision Quad Operational Amplifier; ComponentAvailability: Obsolete
footprint FK020 (Leadless Chip Carrier; 20 Terminals; Body 8.9 x 8.9 mm)
pins: 1 NC, 2 OUT (out), 3 IN- (in), 4 IN+ (in), 5 NC, 6 V+ (power), 7 NC, 8 IN+ (in), 9 IN- (in), 10 OUT (out), 11 NC, 12 OUT (out), 13 IN- (in), 14 IN+ (in), 15 NC, 16 V- (power), 17 NC, 18 IN+ (in), 19 IN- (in), 20 OUT (out)

## TLC27M9MJ
designator U?
LinCMOS Precision Quad Operational Amplifier; ComponentAvailability: Obsolete
footprint J014 (DIP; 14 Leads; Row Spacing 7.62 mm; Pitch 2.54 mm)
3D model J014 (DIP; 14 Leads; Row Spacing 7.62 mm; Pitch 2.54 mm)
pins on every part: 4 V+ (power), 11 V- (power)
part A pins: 1 OUT (out), 2 IN- (in), 3 IN+ (in)
part B pins: 5 IN+ (in), 6 IN- (in), 7 OUT (out)
part C pins: 8 OUT (out), 9 IN- (in), 10 IN+ (in)
part D pins: 12 IN+ (in), 13 IN- (in), 14 OUT (out)

## TLC271ACD
designator U?
LinCMOS Programmable Low-Power Operational Amplifier
footprint D008_L (SOIC, 8-Leads, Body 4.9x3.9mm, Pitch 1.27mm, IPC High Density)
footprint D008_M (SOIC, 8-Leads, Body 4.9x3.9mm, Pitch 1.27mm, IPC Low Density)
footprint D008_M (SOIC, 8-Leads, Body 4.9x3.9mm, Pitch 1.27mm, IPC Low Density)
3D model D008 (8-Pin Small Outline Integrated Circuit 1.27 mm Pitch)
pins: 1 OS N1, 2 IN- (in), 3 IN+ (in), 4 V- (power), 5 OS N2, 6 OUT (out), 7 V+ (power), 8 BSEL (in)

## TLC271ACDR
designator U?
LinCMOS Programmable Low-Power Operational Amplifier
footprint D008_L (SOIC, 8-Leads, Body 4.9x3.9mm, Pitch 1.27mm, IPC High Density)
footprint D008_M (SOIC, 8-Leads, Body 4.9x3.9mm, Pitch 1.27mm, IPC Low Density)
footprint D008_M (SOIC, 8-Leads, Body 4.9x3.9mm, Pitch 1.27mm, IPC Low Density)
3D model D008 (8-Pin Small Outline Integrated Circuit 1.27 mm Pitch)
pins: 1 OS N1, 2 IN- (in), 3 IN+ (in), 4 V- (power), 5 OS N2, 6 OUT (out), 7 V+ (power), 8 BSEL (in)

## TLC271ACJG
designator U?
LinCMOS Programmable Low-Power Operational Amplifier
footprint JG008 (DIP; 8 Leads; Row Spacing 7.62 mm; Pitch 2.54 mm)
3D model JG008 (DIP; 8 Leads; Row Spacing 7.62 mm; Pitch 2.54 mm)
pins: 1 OS N1, 2 IN- (in), 3 IN+ (in), 4 V- (power), 5 OS N2, 6 OUT (out), 7 V+ (power), 8 BSEL (in)

## TLC271ACP
designator U?
LinCMOS Programmable Low-Power Operational Amplifier
footprint P008 (DIP; 8 Leads; Row Spacing 7.62 mm; Pitch 2.54 mm)
3D model P008 (DIP; 8 Leads; Row Spacing 7.62 mm; Pitch 2.54 mm)
pins: 1 OS N1, 2 IN- (in), 3 IN+ (in), 4 V- (power), 5 OS N2, 6 OUT (out), 7 V+ (power), 8 BSEL (in)

## TLC271AID
designator U?
LinCMOS Programmable Low-Power Operational Amplifier
footprint D008_L (SOIC, 8-Leads, Body 4.9x3.9mm, Pitch 1.27mm, IPC High Density)
footprint D008_M (SOIC, 8-Leads, Body 4.9x3.9mm, Pitch 1.27mm, IPC Low Density)
footprint D008_M (SOIC, 8-Leads, Body 4.9x3.9mm, Pitch 1.27mm, IPC Low Density)
3D model D008 (8-Pin Small Outline Integrated Circuit 1.27 mm Pitch)
pins: 1 OS N1, 2 IN- (in), 3 IN+ (in), 4 V- (power), 5 OS N2, 6 OUT (out), 7 V+ (power), 8 BSEL (in)

## TLC271AIDR
designator U?
LinCMOS Programmable Low-Power Operational Amplifier
footprint D008_L (SOIC, 8-Leads, Body 4.9x3.9mm, Pitch 1.27mm, IPC High Density)
footprint D008_M (SOIC, 8-Leads, Body 4.9x3.9mm, Pitch 1.27mm, IPC Low Density)
footprint D008_M (SOIC, 8-Leads, Body 4.9x3.9mm, Pitch 1.27mm, IPC Low Density)
3D model D008 (8-Pin Small Outline Integrated Circuit 1.27 mm Pitch)
pins: 1 OS N1, 2 IN- (in), 3 IN+ (in), 4 V- (power), 5 OS N2, 6 OUT (out), 7 V+ (power), 8 BSEL (in)

## TLC271AIJG
designator U?
LinCMOS Programmable Low-Power Operational Amplifier
footprint JG008 (DIP; 8 Leads; Row Spacing 7.62 mm; Pitch 2.54 mm)
3D model JG008 (DIP; 8 Leads; Row Spacing 7.62 mm; Pitch 2.54 mm)
pins: 1 OS N1, 2 IN- (in), 3 IN+ (in), 4 V- (power), 5 OS N2, 6 OUT (out), 7 V+ (power), 8 BSEL (in)

## TLC271AIP
designator U?
LinCMOS Programmable Low-Power Operational Amplifier
footprint P008 (DIP; 8 Leads; Row Spacing 7.62 mm; Pitch 2.54 mm)
3D model P008 (DIP; 8 Leads; Row Spacing 7.62 mm; Pitch 2.54 mm)
pins: 1 OS N1, 2 IN- (in), 3 IN+ (in), 4 V- (power), 5 OS N2, 6 OUT (out), 7 V+ (power), 8 BSEL (in)

## TLC271BCD
designator U?
LinCMOS Programmable Low-Power Operational Amplifier
footprint D008_L (SOIC, 8-Leads, Body 4.9x3.9mm, Pitch 1.27mm, IPC High Density)
footprint D008_M (SOIC, 8-Leads, Body 4.9x3.9mm, Pitch 1.27mm, IPC Low Density)
footprint D008_M (SOIC, 8-Leads, Body 4.9x3.9mm, Pitch 1.27mm, IPC Low Density)
3D model D008 (8-Pin Small Outline Integrated Circuit 1.27 mm Pitch)
pins: 1 OS N1, 2 IN- (in), 3 IN+ (in), 4 V- (power), 5 OS N2, 6 OUT (out), 7 V+ (power), 8 BSEL (in)

## TLC271BCDR
designator U?
LinCMOS Programmable Low-Power Operational Amplifier
footprint D008_L (SOIC, 8-Leads, Body 4.9x3.9mm, Pitch 1.27mm, IPC High Density)
footprint D008_M (SOIC, 8-Leads, Body 4.9x3.9mm, Pitch 1.27mm, IPC Low Density)
footprint D008_M (SOIC, 8-Leads, Body 4.9x3.9mm, Pitch 1.27mm, IPC Low Density)
3D model D008 (8-Pin Small Outline Integrated Circuit 1.27 mm Pitch)
pins: 1 OS N1, 2 IN- (in), 3 IN+ (in), 4 V- (power), 5 OS N2, 6 OUT (out), 7 V+ (power), 8 BSEL (in)

## TLC271BCJG
designator U?
LinCMOS Programmable Low-Power Operational Amplifier
footprint JG008 (DIP; 8 Leads; Row Spacing 7.62 mm; Pitch 2.54 mm)
3D model JG008 (DIP; 8 Leads; Row Spacing 7.62 mm; Pitch 2.54 mm)
pins: 1 OS N1, 2 IN- (in), 3 IN+ (in), 4 V- (power), 5 OS N2, 6 OUT (out), 7 V+ (power), 8 BSEL (in)

## TLC271BCP
designator U?
LinCMOS Programmable Low-Power Operational Amplifier
footprint P008 (DIP; 8 Leads; Row Spacing 7.62 mm; Pitch 2.54 mm)
3D model P008 (DIP; 8 Leads; Row Spacing 7.62 mm; Pitch 2.54 mm)
pins: 1 OS N1, 2 IN- (in), 3 IN+ (in), 4 V- (power), 5 OS N2, 6 OUT (out), 7 V+ (power), 8 BSEL (in)

## TLC271BID
designator U?
LinCMOS Programmable Low-Power Operational Amplifier
footprint D008_L (SOIC, 8-Leads, Body 4.9x3.9mm, Pitch 1.27mm, IPC High Density)
footprint D008_M (SOIC, 8-Leads, Body 4.9x3.9mm, Pitch 1.27mm, IPC Low Density)
footprint D008_M (SOIC, 8-Leads, Body 4.9x3.9mm, Pitch 1.27mm, IPC Low Density)
3D model D008 (8-Pin Small Outline Integrated Circuit 1.27 mm Pitch)
pins: 1 OS N1, 2 IN- (in), 3 IN+ (in), 4 V- (power), 5 OS N2, 6 OUT (out), 7 V+ (power), 8 BSEL (in)

## TLC271BIDR
designator U?
LinCMOS Programmable Low-Power Operational Amplifier
footprint D008_L (SOIC, 8-Leads, Body 4.9x3.9mm, Pitch 1.27mm, IPC High Density)
footprint D008_M (SOIC, 8-Leads, Body 4.9x3.9mm, Pitch 1.27mm, IPC Low Density)
footprint D008_M (SOIC, 8-Leads, Body 4.9x3.9mm, Pitch 1.27mm, IPC Low Density)
3D model D008 (8-Pin Small Outline Integrated Circuit 1.27 mm Pitch)
pins: 1 OS N1, 2 IN- (in), 3 IN+ (in), 4 V- (power), 5 OS N2, 6 OUT (out), 7 V+ (power), 8 BSEL (in)

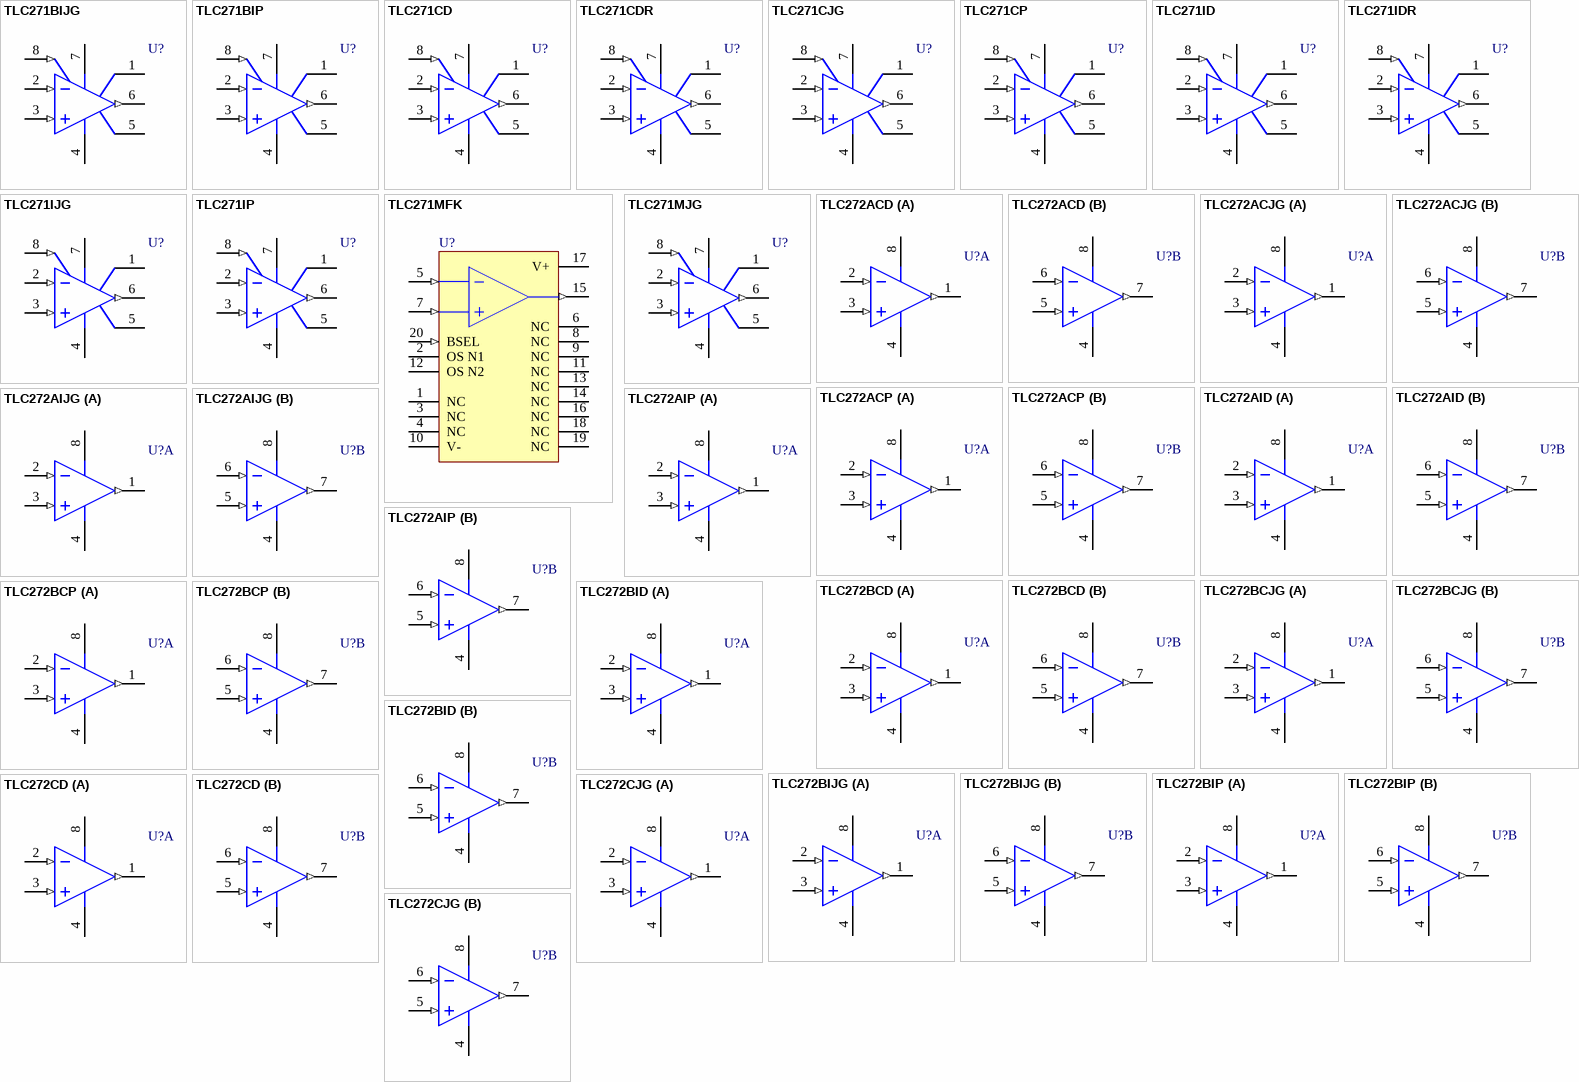
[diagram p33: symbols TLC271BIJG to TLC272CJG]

## TLC271BIJG
designator U?
LinCMOS Programmable Low-Power Operational Amplifier
footprint JG008 (DIP; 8 Leads; Row Spacing 7.62 mm; Pitch 2.54 mm)
3D model JG008 (DIP; 8 Leads; Row Spacing 7.62 mm; Pitch 2.54 mm)
pins: 1 OS N1, 2 IN- (in), 3 IN+ (in), 4 V- (power), 5 OS N2, 6 OUT (out), 7 V+ (power), 8 BSEL (in)

## TLC271BIP
designator U?
LinCMOS Programmable Low-Power Operational Amplifier
footprint P008 (DIP; 8 Leads; Row Spacing 7.62 mm; Pitch 2.54 mm)
3D model P008 (DIP; 8 Leads; Row Spacing 7.62 mm; Pitch 2.54 mm)
pins: 1 OS N1, 2 IN- (in), 3 IN+ (in), 4 V- (power), 5 OS N2, 6 OUT (out), 7 V+ (power), 8 BSEL (in)

## TLC271CD
designator U?
LinCMOS Programmable Low-Power Operational Amplifier
footprint D008_L (SOIC, 8-Leads, Body 4.9x3.9mm, Pitch 1.27mm, IPC High Density)
footprint D008_M (SOIC, 8-Leads, Body 4.9x3.9mm, Pitch 1.27mm, IPC Low Density)
footprint D008_M (SOIC, 8-Leads, Body 4.9x3.9mm, Pitch 1.27mm, IPC Low Density)
3D model D008 (8-Pin Small Outline Integrated Circuit 1.27 mm Pitch)
pins: 1 OS N1, 2 IN- (in), 3 IN+ (in), 4 V- (power), 5 OS N2, 6 OUT (out), 7 V+ (power), 8 BSEL (in)

## TLC271CDR
designator U?
LinCMOS Programmable Low-Power Operational Amplifier
footprint D008_L (SOIC, 8-Leads, Body 4.9x3.9mm, Pitch 1.27mm, IPC High Density)
footprint D008_M (SOIC, 8-Leads, Body 4.9x3.9mm, Pitch 1.27mm, IPC Low Density)
footprint D008_M (SOIC, 8-Leads, Body 4.9x3.9mm, Pitch 1.27mm, IPC Low Density)
3D model D008 (8-Pin Small Outline Integrated Circuit 1.27 mm Pitch)
pins: 1 OS N1, 2 IN- (in), 3 IN+ (in), 4 V- (power), 5 OS N2, 6 OUT (out), 7 V+ (power), 8 BSEL (in)

## TLC271CJG
designator U?
LinCMOS Programmable Low-Power Operational Amplifier
footprint JG008 (DIP; 8 Leads; Row Spacing 7.62 mm; Pitch 2.54 mm)
3D model JG008 (DIP; 8 Leads; Row Spacing 7.62 mm; Pitch 2.54 mm)
pins: 1 OS N1, 2 IN- (in), 3 IN+ (in), 4 V- (power), 5 OS N2, 6 OUT (out), 7 V+ (power), 8 BSEL (in)

## TLC271CP
designator U?
LinCMOS Programmable Low-Power Operational Amplifier
footprint P008 (DIP; 8 Leads; Row Spacing 7.62 mm; Pitch 2.54 mm)
3D model P008 (DIP; 8 Leads; Row Spacing 7.62 mm; Pitch 2.54 mm)
pins: 1 OS N1, 2 IN- (in), 3 IN+ (in), 4 V- (power), 5 OS N2, 6 OUT (out), 7 V+ (power), 8 BSEL (in)

## TLC271ID
designator U?
LinCMOS Programmable Low-Power Operational Amplifier
footprint D008_L (SOIC, 8-Leads, Body 4.9x3.9mm, Pitch 1.27mm, IPC High Density)
footprint D008_M (SOIC, 8-Leads, Body 4.9x3.9mm, Pitch 1.27mm, IPC Low Density)
footprint D008_M (SOIC, 8-Leads, Body 4.9x3.9mm, Pitch 1.27mm, IPC Low Density)
3D model D008 (8-Pin Small Outline Integrated Circuit 1.27 mm Pitch)
pins: 1 OS N1, 2 IN- (in), 3 IN+ (in), 4 V- (power), 5 OS N2, 6 OUT (out), 7 V+ (power), 8 BSEL (in)

## TLC271IDR
designator U?
LinCMOS Programmable Low-Power Operational Amplifier
footprint D008_L (SOIC, 8-Leads, Body 4.9x3.9mm, Pitch 1.27mm, IPC High Density)
footprint D008_M (SOIC, 8-Leads, Body 4.9x3.9mm, Pitch 1.27mm, IPC Low Density)
footprint D008_M (SOIC, 8-Leads, Body 4.9x3.9mm, Pitch 1.27mm, IPC Low Density)
3D model D008 (8-Pin Small Outline Integrated Circuit 1.27 mm Pitch)
pins: 1 OS N1, 2 IN- (in), 3 IN+ (in), 4 V- (power), 5 OS N2, 6 OUT (out), 7 V+ (power), 8 BSEL (in)

## TLC271IJG
designator U?
LinCMOS Programmable Low-Power Operational Amplifier
footprint JG008 (DIP; 8 Leads; Row Spacing 7.62 mm; Pitch 2.54 mm)
3D model JG008 (DIP; 8 Leads; Row Spacing 7.62 mm; Pitch 2.54 mm)
pins: 1 OS N1, 2 IN- (in), 3 IN+ (in), 4 V- (power), 5 OS N2, 6 OUT (out), 7 V+ (power), 8 BSEL (in)

## TLC271IP
designator U?
LinCMOS Programmable Low-Power Operational Amplifier
footprint P008 (DIP; 8 Leads; Row Spacing 7.62 mm; Pitch 2.54 mm)
3D model P008 (DIP; 8 Leads; Row Spacing 7.62 mm; Pitch 2.54 mm)
pins: 1 OS N1, 2 IN- (in), 3 IN+ (in), 4 V- (power), 5 OS N2, 6 OUT (out), 7 V+ (power), 8 BSEL (in)

## TLC271MFK
designator U?
LinCMOS Programmable Low-Power Operational Amplifier
footprint FK020 (Leadless Chip Carrier; 20 Terminals; Body 8.9 x 8.9 mm)
pins: 1 NC, 2 OS N1, 3 NC, 4 NC, 5 IN- (in), 6 NC, 7 IN+ (in), 8 NC, 9 NC, 10 V- (power), 11 NC, 12 OS N2, 13 NC, 14 NC, 15 OUT (out), 16 NC, 17 V+ (power), 18 NC, 19 NC, 20 BSEL (in)

## TLC271MJG
designator U?
LinCMOS Programmable Low-Power Operational Amplifier; ComponentAvailability: Obsolete
footprint JG008 (DIP; 8 Leads; Row Spacing 7.62 mm; Pitch 2.54 mm)
3D model JG008 (DIP; 8 Leads; Row Spacing 7.62 mm; Pitch 2.54 mm)
pins: 1 OS N1, 2 IN- (in), 3 IN+ (in), 4 V- (power), 5 OS N2, 6 OUT (out), 7 V+ (power), 8 BSEL (in)

## TLC272ACD
designator U?
LinCMOS Precision Dual Operational Amplifier
footprint D008_L (SOIC, 8-Leads, Body 4.9x3.9mm, Pitch 1.27mm, IPC High Density)
footprint D008_M (SOIC, 8-Leads, Body 4.9x3.9mm, Pitch 1.27mm, IPC Low Density)
footprint D008_M (SOIC, 8-Leads, Body 4.9x3.9mm, Pitch 1.27mm, IPC Low Density)
3D model D008 (8-Pin Small Outline Integrated Circuit 1.27 mm Pitch)
pins on every part: 4 GND (power), 8 VDD (power)
part A pins: 1 OUT (out), 2 IN- (in), 3 IN+ (in)
part B pins: 5 IN+ (in), 6 IN- (in), 7 OUT (out)

## TLC272ACJG
designator U?
LinCMOS Precision Dual Operational Amplifier
footprint JG008 (DIP; 8 Leads; Row Spacing 7.62 mm; Pitch 2.54 mm)
3D model JG008 (DIP; 8 Leads; Row Spacing 7.62 mm; Pitch 2.54 mm)
pins on every part: 4 GND (power), 8 VDD (power)
part A pins: 1 OUT (out), 2 IN- (in), 3 IN+ (in)
part B pins: 5 IN+ (in), 6 IN- (in), 7 OUT (out)

## TLC272ACP
designator U?
LinCMOS Precision Dual Operational Amplifier
footprint P008 (DIP; 8 Leads; Row Spacing 7.62 mm; Pitch 2.54 mm)
3D model P008 (DIP; 8 Leads; Row Spacing 7.62 mm; Pitch 2.54 mm)
pins on every part: 4 GND (power), 8 VDD (power)
part A pins: 1 OUT (out), 2 IN- (in), 3 IN+ (in)
part B pins: 5 IN+ (in), 6 IN- (in), 7 OUT (out)

## TLC272AID
designator U?
LinCMOS Precision Dual Operational Amplifier
footprint D008_L (SOIC, 8-Leads, Body 4.9x3.9mm, Pitch 1.27mm, IPC High Density)
footprint D008_M (SOIC, 8-Leads, Body 4.9x3.9mm, Pitch 1.27mm, IPC Low Density)
footprint D008_M (SOIC, 8-Leads, Body 4.9x3.9mm, Pitch 1.27mm, IPC Low Density)
3D model D008 (8-Pin Small Outline Integrated Circuit 1.27 mm Pitch)
pins on every part: 4 GND (power), 8 VDD (power)
part A pins: 1 OUT (out), 2 IN- (in), 3 IN+ (in)
part B pins: 5 IN+ (in), 6 IN- (in), 7 OUT (out)

## TLC272AIJG
designator U?
LinCMOS Precision Dual Operational Amplifier
footprint JG008 (DIP; 8 Leads; Row Spacing 7.62 mm; Pitch 2.54 mm)
3D model JG008 (DIP; 8 Leads; Row Spacing 7.62 mm; Pitch 2.54 mm)
pins on every part: 4 GND (power), 8 VDD (power)
part A pins: 1 OUT (out), 2 IN- (in), 3 IN+ (in)
part B pins: 5 IN+ (in), 6 IN- (in), 7 OUT (out)

## TLC272AIP
designator U?
LinCMOS Precision Dual Operational Amplifier
footprint P008 (DIP; 8 Leads; Row Spacing 7.62 mm; Pitch 2.54 mm)
3D model P008 (DIP; 8 Leads; Row Spacing 7.62 mm; Pitch 2.54 mm)
pins on every part: 4 GND (power), 8 VDD (power)
part A pins: 1 OUT (out), 2 IN- (in), 3 IN+ (in)
part B pins: 5 IN+ (in), 6 IN- (in), 7 OUT (out)

## TLC272BCD
designator U?
LinCMOS Precision Dual Operational Amplifier
footprint D008_L (SOIC, 8-Leads, Body 4.9x3.9mm, Pitch 1.27mm, IPC High Density)
footprint D008_M (SOIC, 8-Leads, Body 4.9x3.9mm, Pitch 1.27mm, IPC Low Density)
footprint D008_M (SOIC, 8-Leads, Body 4.9x3.9mm, Pitch 1.27mm, IPC Low Density)
3D model D008 (8-Pin Small Outline Integrated Circuit 1.27 mm Pitch)
pins on every part: 4 GND (power), 8 VDD (power)
part A pins: 1 OUT (out), 2 IN- (in), 3 IN+ (in)
part B pins: 5 IN+ (in), 6 IN- (in), 7 OUT (out)

## TLC272BCJG
designator U?
LinCMOS Precision Dual Operational Amplifier
footprint JG008 (DIP; 8 Leads; Row Spacing 7.62 mm; Pitch 2.54 mm)
3D model JG008 (DIP; 8 Leads; Row Spacing 7.62 mm; Pitch 2.54 mm)
pins on every part: 4 GND (power), 8 VDD (power)
part A pins: 1 OUT (out), 2 IN- (in), 3 IN+ (in)
part B pins: 5 IN+ (in), 6 IN- (in), 7 OUT (out)

## TLC272BCP
designator U?
LinCMOS Precision Dual Operational Amplifier
footprint P008 (DIP; 8 Leads; Row Spacing 7.62 mm; Pitch 2.54 mm)
3D model P008 (DIP; 8 Leads; Row Spacing 7.62 mm; Pitch 2.54 mm)
pins on every part: 4 GND (power), 8 VDD (power)
part A pins: 1 OUT (out), 2 IN- (in), 3 IN+ (in)
part B pins: 5 IN+ (in), 6 IN- (in), 7 OUT (out)

## TLC272BID
designator U?
LinCMOS Precision Dual Operational Amplifier
footprint D008_L (SOIC, 8-Leads, Body 4.9x3.9mm, Pitch 1.27mm, IPC High Density)
footprint D008_M (SOIC, 8-Leads, Body 4.9x3.9mm, Pitch 1.27mm, IPC Low Density)
footprint D008_M (SOIC, 8-Leads, Body 4.9x3.9mm, Pitch 1.27mm, IPC Low Density)
3D model D008 (8-Pin Small Outline Integrated Circuit 1.27 mm Pitch)
pins on every part: 4 GND (power), 8 VDD (power)
part A pins: 1 OUT (out), 2 IN- (in), 3 IN+ (in)
part B pins: 5 IN+ (in), 6 IN- (in), 7 OUT (out)

## TLC272BIJG
designator U?
LinCMOS Precision Dual Operational Amplifier
footprint JG008 (DIP; 8 Leads; Row Spacing 7.62 mm; Pitch 2.54 mm)
3D model JG008 (DIP; 8 Leads; Row Spacing 7.62 mm; Pitch 2.54 mm)
pins on every part: 4 GND (power), 8 VDD (power)
part A pins: 1 OUT (out), 2 IN- (in), 3 IN+ (in)
part B pins: 5 IN+ (in), 6 IN- (in), 7 OUT (out)

## TLC272BIP
designator U?
LinCMOS Precision Dual Operational Amplifier
footprint P008 (DIP; 8 Leads; Row Spacing 7.62 mm; Pitch 2.54 mm)
3D model P008 (DIP; 8 Leads; Row Spacing 7.62 mm; Pitch 2.54 mm)
pins on every part: 4 GND (power), 8 VDD (power)
part A pins: 1 OUT (out), 2 IN- (in), 3 IN+ (in)
part B pins: 5 IN+ (in), 6 IN- (in), 7 OUT (out)

## TLC272CD
designator U?
LinCMOS Precision Dual Operational Amplifier
footprint D008_L (SOIC, 8-Leads, Body 4.9x3.9mm, Pitch 1.27mm, IPC High Density)
footprint D008_M (SOIC, 8-Leads, Body 4.9x3.9mm, Pitch 1.27mm, IPC Low Density)
footprint D008_M (SOIC, 8-Leads, Body 4.9x3.9mm, Pitch 1.27mm, IPC Low Density)
3D model D008 (8-Pin Small Outline Integrated Circuit 1.27 mm Pitch)
pins on every part: 4 GND (power), 8 VDD (power)
part A pins: 1 OUT (out), 2 IN- (in), 3 IN+ (in)
part B pins: 5 IN+ (in), 6 IN- (in), 7 OUT (out)

## TLC272CJG
designator U?
LinCMOS Precision Dual Operational Amplifier
footprint JG008 (DIP; 8 Leads; Row Spacing 7.62 mm; Pitch 2.54 mm)
3D model JG008 (DIP; 8 Leads; Row Spacing 7.62 mm; Pitch 2.54 mm)
pins on every part: 4 GND (power), 8 VDD (power)
part A pins: 1 OUT (out), 2 IN- (in), 3 IN+ (in)
part B pins: 5 IN+ (in), 6 IN- (in), 7 OUT (out)

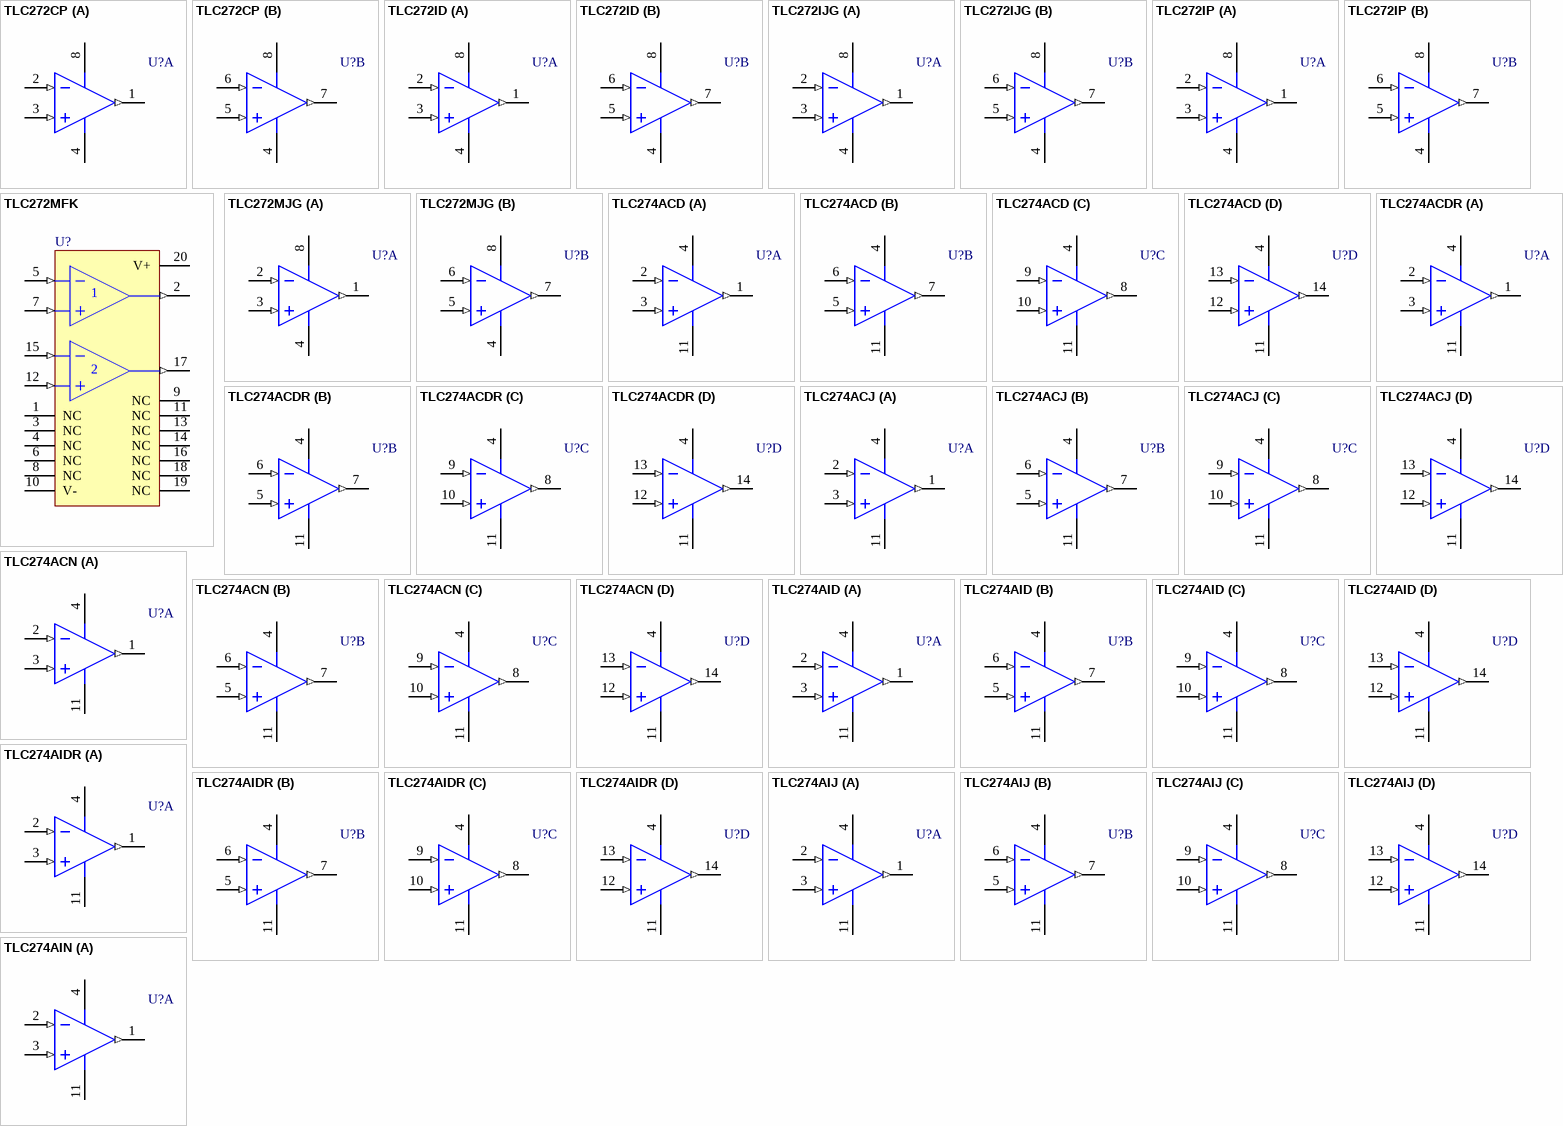
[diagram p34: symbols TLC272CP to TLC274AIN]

## TLC272CP
designator U?
LinCMOS Precision Dual Operational Amplifier
footprint P008 (DIP; 8 Leads; Row Spacing 7.62 mm; Pitch 2.54 mm)
3D model P008 (DIP; 8 Leads; Row Spacing 7.62 mm; Pitch 2.54 mm)
pins on every part: 4 GND (power), 8 VDD (power)
part A pins: 1 OUT (out), 2 IN- (in), 3 IN+ (in)
part B pins: 5 IN+ (in), 6 IN- (in), 7 OUT (out)

## TLC272ID
designator U?
LinCMOS Precision Dual Operational Amplifier
footprint D008_L (SOIC, 8-Leads, Body 4.9x3.9mm, Pitch 1.27mm, IPC High Density)
footprint D008_M (SOIC, 8-Leads, Body 4.9x3.9mm, Pitch 1.27mm, IPC Low Density)
footprint D008_M (SOIC, 8-Leads, Body 4.9x3.9mm, Pitch 1.27mm, IPC Low Density)
3D model D008 (8-Pin Small Outline Integrated Circuit 1.27 mm Pitch)
pins on every part: 4 GND (power), 8 VDD (power)
part A pins: 1 OUT (out), 2 IN- (in), 3 IN+ (in)
part B pins: 5 IN+ (in), 6 IN- (in), 7 OUT (out)

## TLC272IJG
designator U?
LinCMOS Precision Dual Operational Amplifier
footprint JG008 (DIP; 8 Leads; Row Spacing 7.62 mm; Pitch 2.54 mm)
3D model JG008 (DIP; 8 Leads; Row Spacing 7.62 mm; Pitch 2.54 mm)
pins on every part: 4 GND (power), 8 VDD (power)
part A pins: 1 OUT (out), 2 IN- (in), 3 IN+ (in)
part B pins: 5 IN+ (in), 6 IN- (in), 7 OUT (out)

## TLC272IP
designator U?
LinCMOS Precision Dual Operational Amplifier
footprint P008 (DIP; 8 Leads; Row Spacing 7.62 mm; Pitch 2.54 mm)
3D model P008 (DIP; 8 Leads; Row Spacing 7.62 mm; Pitch 2.54 mm)
pins on every part: 4 GND (power), 8 VDD (power)
part A pins: 1 OUT (out), 2 IN- (in), 3 IN+ (in)
part B pins: 5 IN+ (in), 6 IN- (in), 7 OUT (out)

## TLC272MFK
designator U?
LinCMOS Precision Dual Operational Amplifier; ComponentAvailability: Obsolete
footprint FK020 (Leadless Chip Carrier; 20 Terminals; Body 8.9 x 8.9 mm)
pins: 1 NC, 2 OUT (out), 3 NC, 4 NC, 5 IN- (in), 6 NC, 7 IN+ (in), 8 NC, 9 NC, 10 V- (power), 11 NC, 12 IN+ (in), 13 NC, 14 NC, 15 IN- (in), 16 NC, 17 OUT (out), 18 NC, 19 NC, 20 V+ (power)

## TLC272MJG
designator U?
LinCMOS Precision Dual Operational Amplifier; ComponentAvailability: Obsolete
footprint JG008 (DIP; 8 Leads; Row Spacing 7.62 mm; Pitch 2.54 mm)
3D model JG008 (DIP; 8 Leads; Row Spacing 7.62 mm; Pitch 2.54 mm)
pins on every part: 4 GND (power), 8 VDD (power)
part A pins: 1 OUT (out), 2 IN- (in), 3 IN+ (in)
part B pins: 5 IN+ (in), 6 IN- (in), 7 OUT (out)

## TLC274ACD
designator U?
LinCMOS Precision Quad Operational Amplifier
footprint D014_N (SOIC, 14-Leads, Body 8.7x3.9mm, Pitch 1.27mm, IPC Medium Density)
footprint D014_L (SOIC, 14-Leads, Body 8.7x3.9mm, Pitch 1.27mm, IPC High Density)
footprint D014_M (SOIC, 14-Leads, Body 8.7x3.9mm, Pitch 1.27mm, IPC Low Density)
3D model D014 (14-Pin Small Outline Integrated Circuit 1.27 mm Pitch)
pins on every part: 4 V+ (power), 11 V- (power)
part A pins: 1 OUT (out), 2 IN- (in), 3 IN+ (in)
part B pins: 5 IN+ (in), 6 IN- (in), 7 OUT (out)
part C pins: 8 OUT (out), 9 IN- (in), 10 IN+ (in)
part D pins: 12 IN+ (in), 13 IN- (in), 14 OUT (out)

## TLC274ACDR
designator U?
LinCMOS Precision Quad Operational Amplifier
footprint D014_N (SOIC, 14-Leads, Body 8.7x3.9mm, Pitch 1.27mm, IPC Medium Density)
footprint D014_L (SOIC, 14-Leads, Body 8.7x3.9mm, Pitch 1.27mm, IPC High Density)
footprint D014_M (SOIC, 14-Leads, Body 8.7x3.9mm, Pitch 1.27mm, IPC Low Density)
3D model D014 (14-Pin Small Outline Integrated Circuit 1.27 mm Pitch)
pins on every part: 4 V+ (power), 11 V- (power)
part A pins: 1 OUT (out), 2 IN- (in), 3 IN+ (in)
part B pins: 5 IN+ (in), 6 IN- (in), 7 OUT (out)
part C pins: 8 OUT (out), 9 IN- (in), 10 IN+ (in)
part D pins: 12 IN+ (in), 13 IN- (in), 14 OUT (out)

## TLC274ACJ
designator U?
LinCMOS Precision Quad Operational Amplifier
footprint J014 (DIP; 14 Leads; Row Spacing 7.62 mm; Pitch 2.54 mm)
3D model J014 (DIP; 14 Leads; Row Spacing 7.62 mm; Pitch 2.54 mm)
pins on every part: 4 V+ (power), 11 V- (power)
part A pins: 1 OUT (out), 2 IN- (in), 3 IN+ (in)
part B pins: 5 IN+ (in), 6 IN- (in), 7 OUT (out)
part C pins: 8 OUT (out), 9 IN- (in), 10 IN+ (in)
part D pins: 12 IN+ (in), 13 IN- (in), 14 OUT (out)

## TLC274ACN
designator U?
LinCMOS Precision Quad Operational Amplifier
footprint N014 (DIP; 14 Leads; Row Spacing 7.62 mm; Pitch 2.54 mm)
3D model N014 (DIP; 14 Leads; Row Spacing 7.62 mm; Pitch 2.54 mm)
pins on every part: 4 V+ (power), 11 V- (power)
part A pins: 1 OUT (out), 2 IN- (in), 3 IN+ (in)
part B pins: 5 IN+ (in), 6 IN- (in), 7 OUT (out)
part C pins: 8 OUT (out), 9 IN- (in), 10 IN+ (in)
part D pins: 12 IN+ (in), 13 IN- (in), 14 OUT (out)

## TLC274AID
designator U?
LinCMOS Precision Quad Operational Amplifier
footprint D014_N (SOIC, 14-Leads, Body 8.7x3.9mm, Pitch 1.27mm, IPC Medium Density)
footprint D014_L (SOIC, 14-Leads, Body 8.7x3.9mm, Pitch 1.27mm, IPC High Density)
footprint D014_M (SOIC, 14-Leads, Body 8.7x3.9mm, Pitch 1.27mm, IPC Low Density)
3D model D014 (14-Pin Small Outline Integrated Circuit 1.27 mm Pitch)
pins on every part: 4 V+ (power), 11 V- (power)
part A pins: 1 OUT (out), 2 IN- (in), 3 IN+ (in)
part B pins: 5 IN+ (in), 6 IN- (in), 7 OUT (out)
part C pins: 8 OUT (out), 9 IN- (in), 10 IN+ (in)
part D pins: 12 IN+ (in), 13 IN- (in), 14 OUT (out)

## TLC274AIDR
designator U?
LinCMOS Precision Quad Operational Amplifier
footprint D014_N (SOIC, 14-Leads, Body 8.7x3.9mm, Pitch 1.27mm, IPC Medium Density)
footprint D014_L (SOIC, 14-Leads, Body 8.7x3.9mm, Pitch 1.27mm, IPC High Density)
footprint D014_M (SOIC, 14-Leads, Body 8.7x3.9mm, Pitch 1.27mm, IPC Low Density)
3D model D014 (14-Pin Small Outline Integrated Circuit 1.27 mm Pitch)
pins on every part: 4 V+ (power), 11 V- (power)
part A pins: 1 OUT (out), 2 IN- (in), 3 IN+ (in)
part B pins: 5 IN+ (in), 6 IN- (in), 7 OUT (out)
part C pins: 8 OUT (out), 9 IN- (in), 10 IN+ (in)
part D pins: 12 IN+ (in), 13 IN- (in), 14 OUT (out)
